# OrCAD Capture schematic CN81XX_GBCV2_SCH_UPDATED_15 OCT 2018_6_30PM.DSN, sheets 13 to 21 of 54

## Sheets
13 13.CN81XX CORE VDD: size B; title: CN81XX CORE VDD
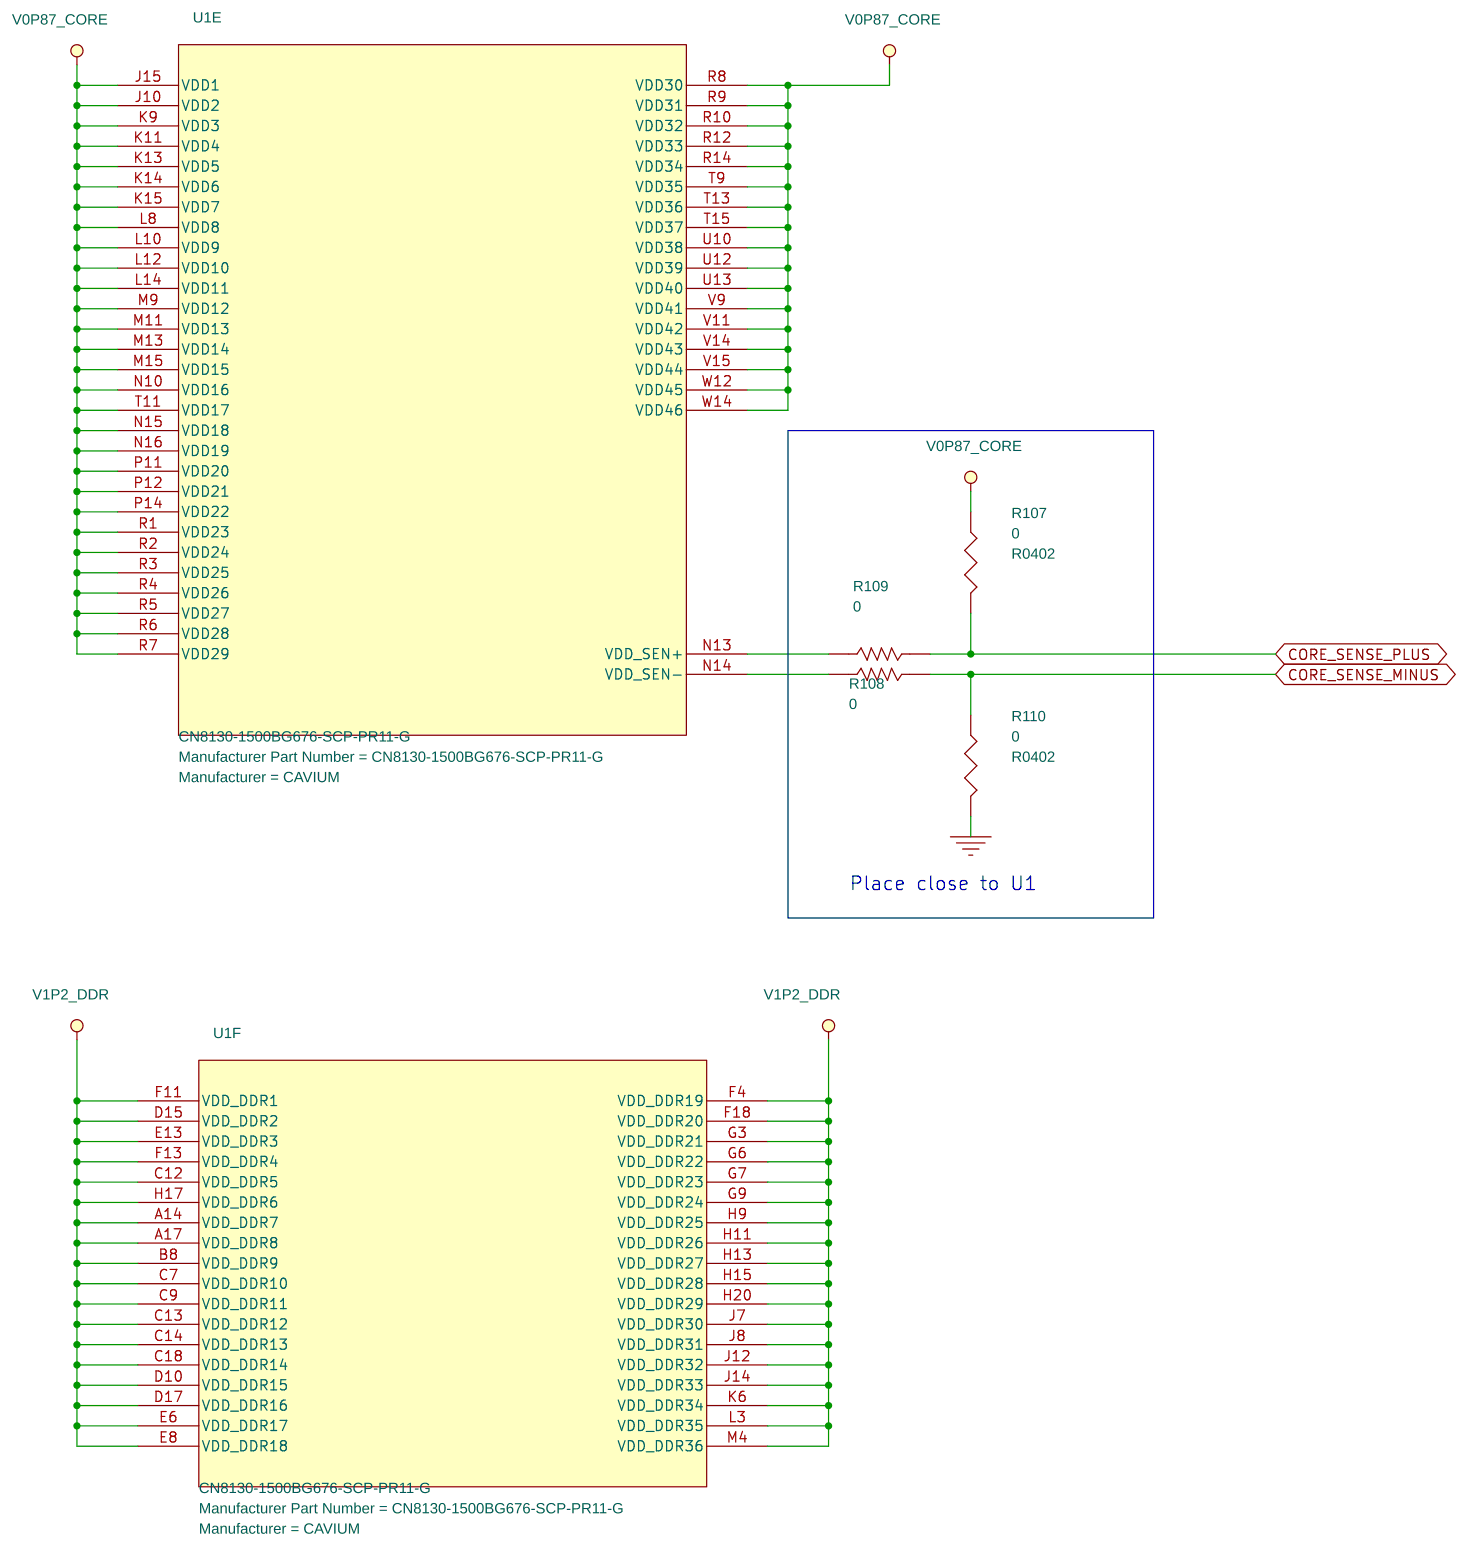
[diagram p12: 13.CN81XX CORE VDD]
14 15.CN81XX QLM & USB SUPPLY: size B; title: CN81XX QLM&USB SUPLY
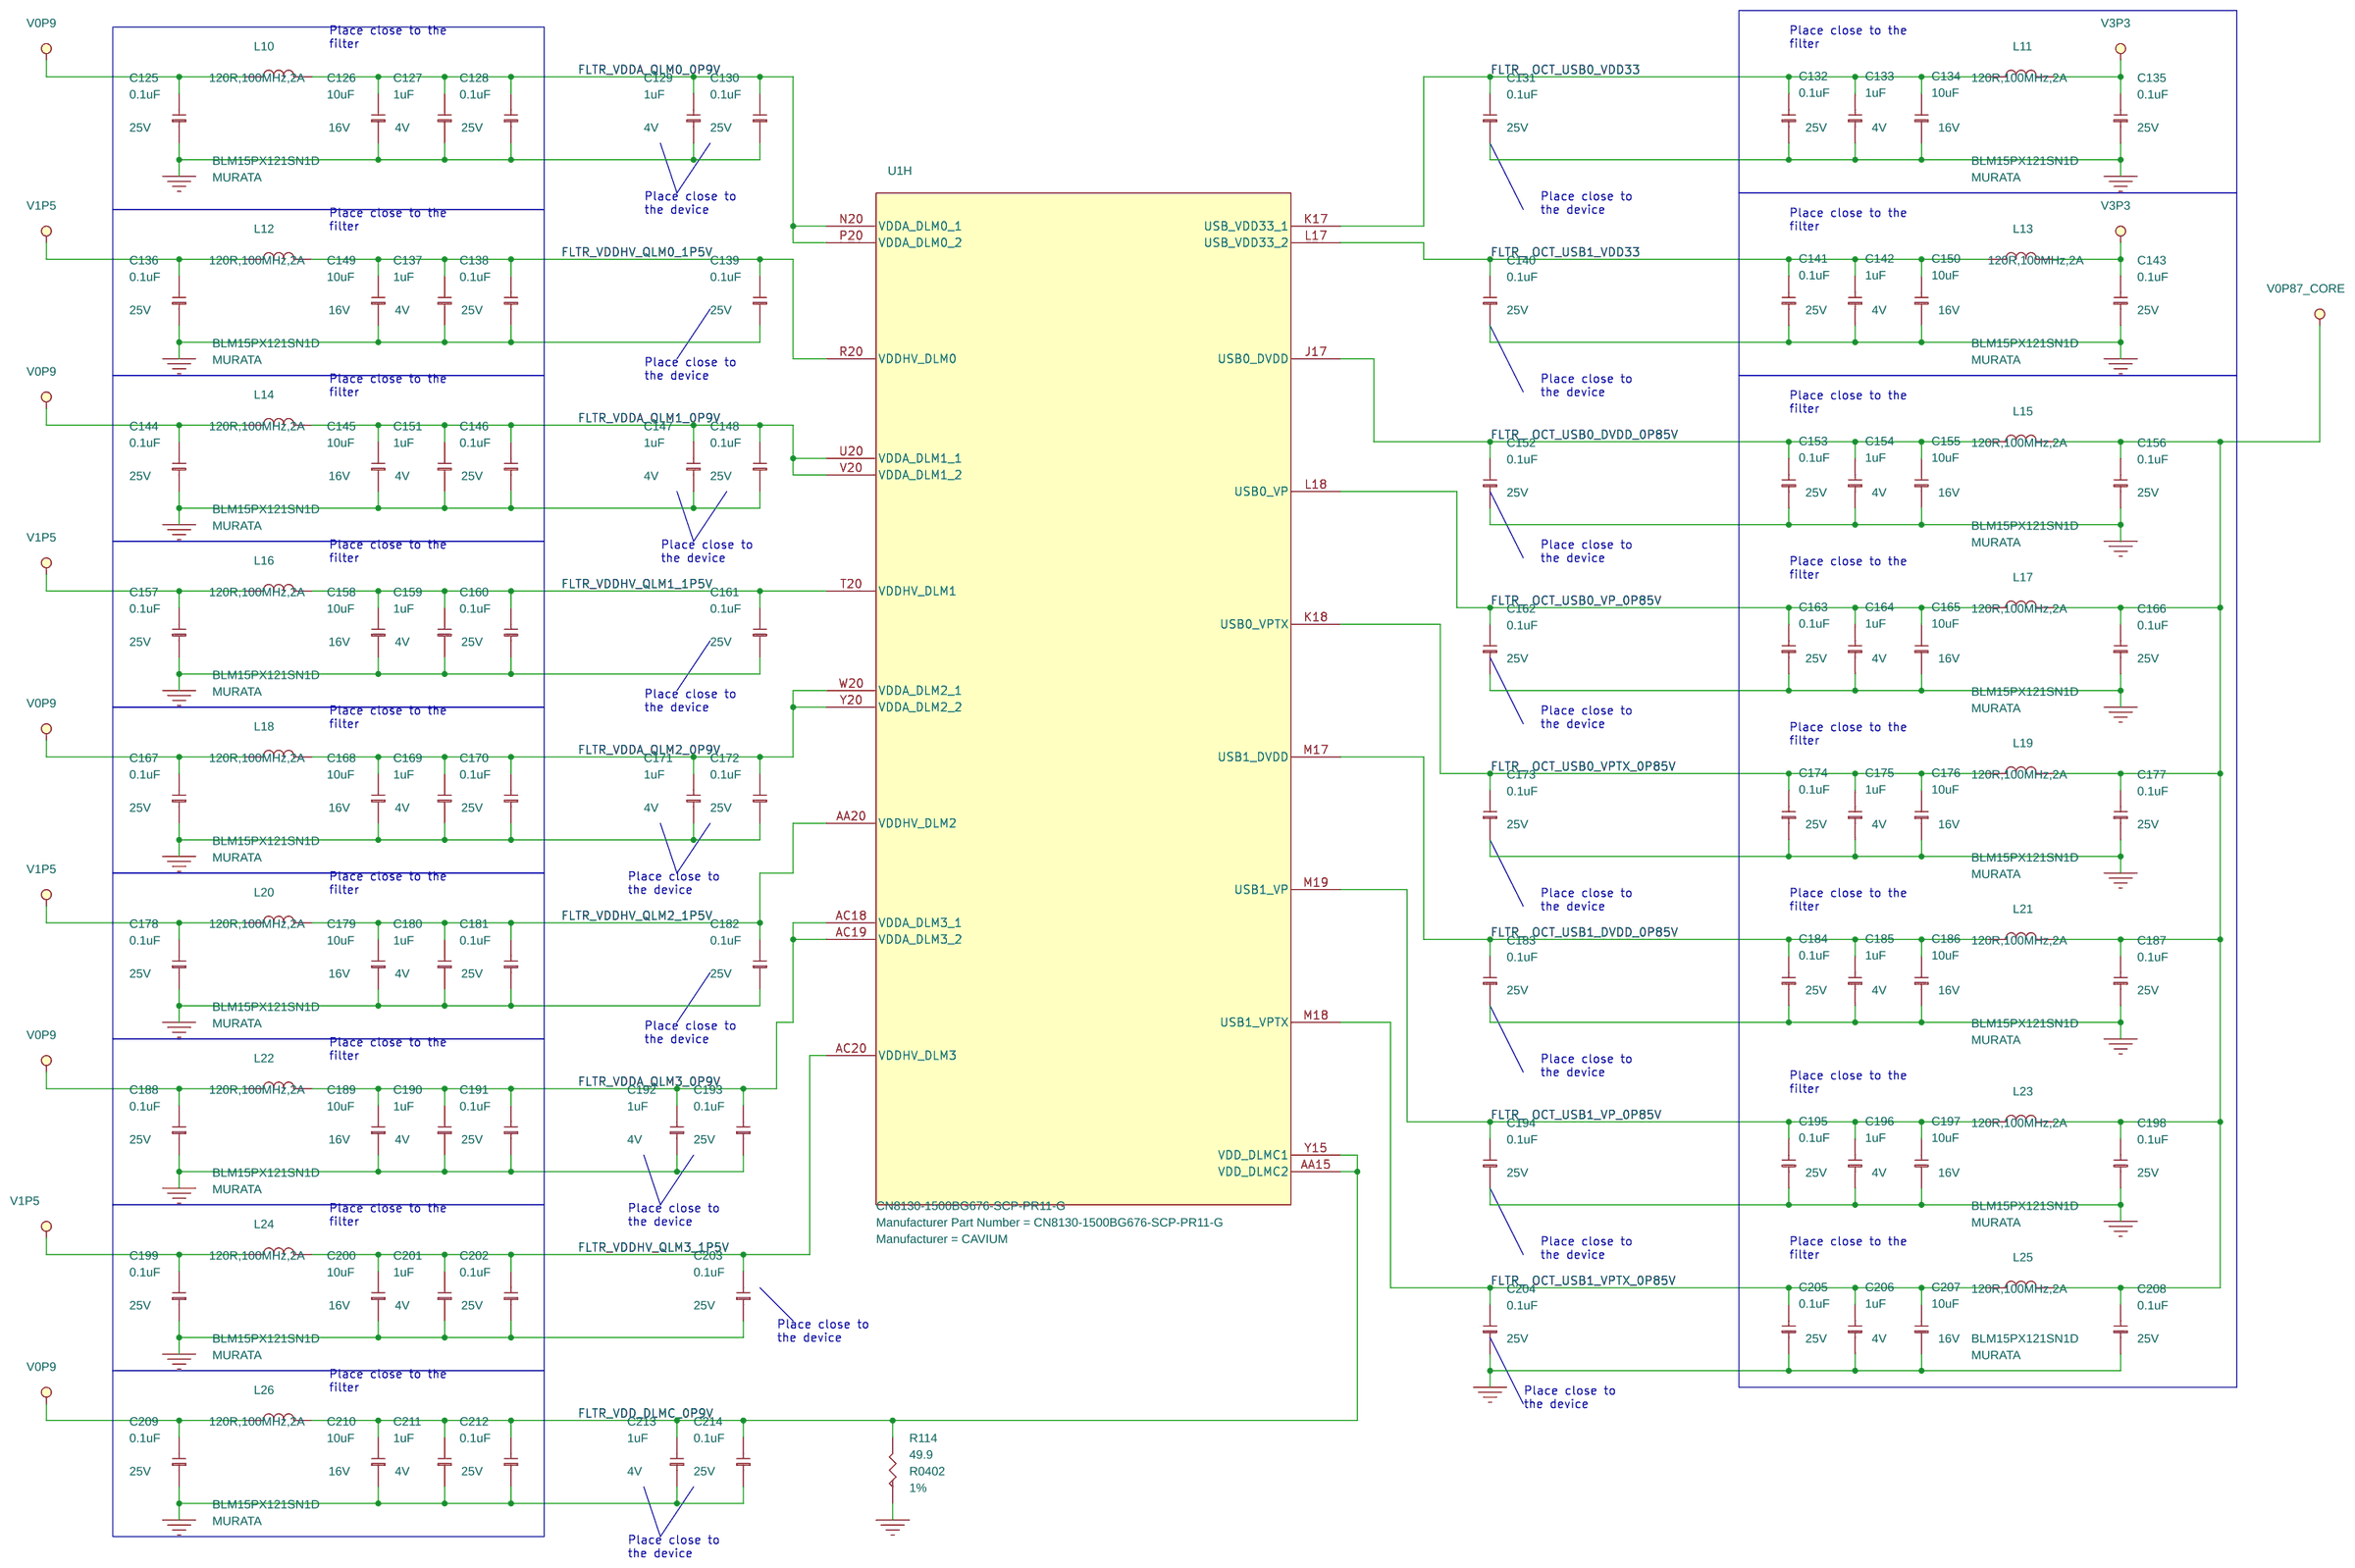
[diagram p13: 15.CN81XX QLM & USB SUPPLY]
15 16.CN81XX GND: size B; title: CN81XX GND
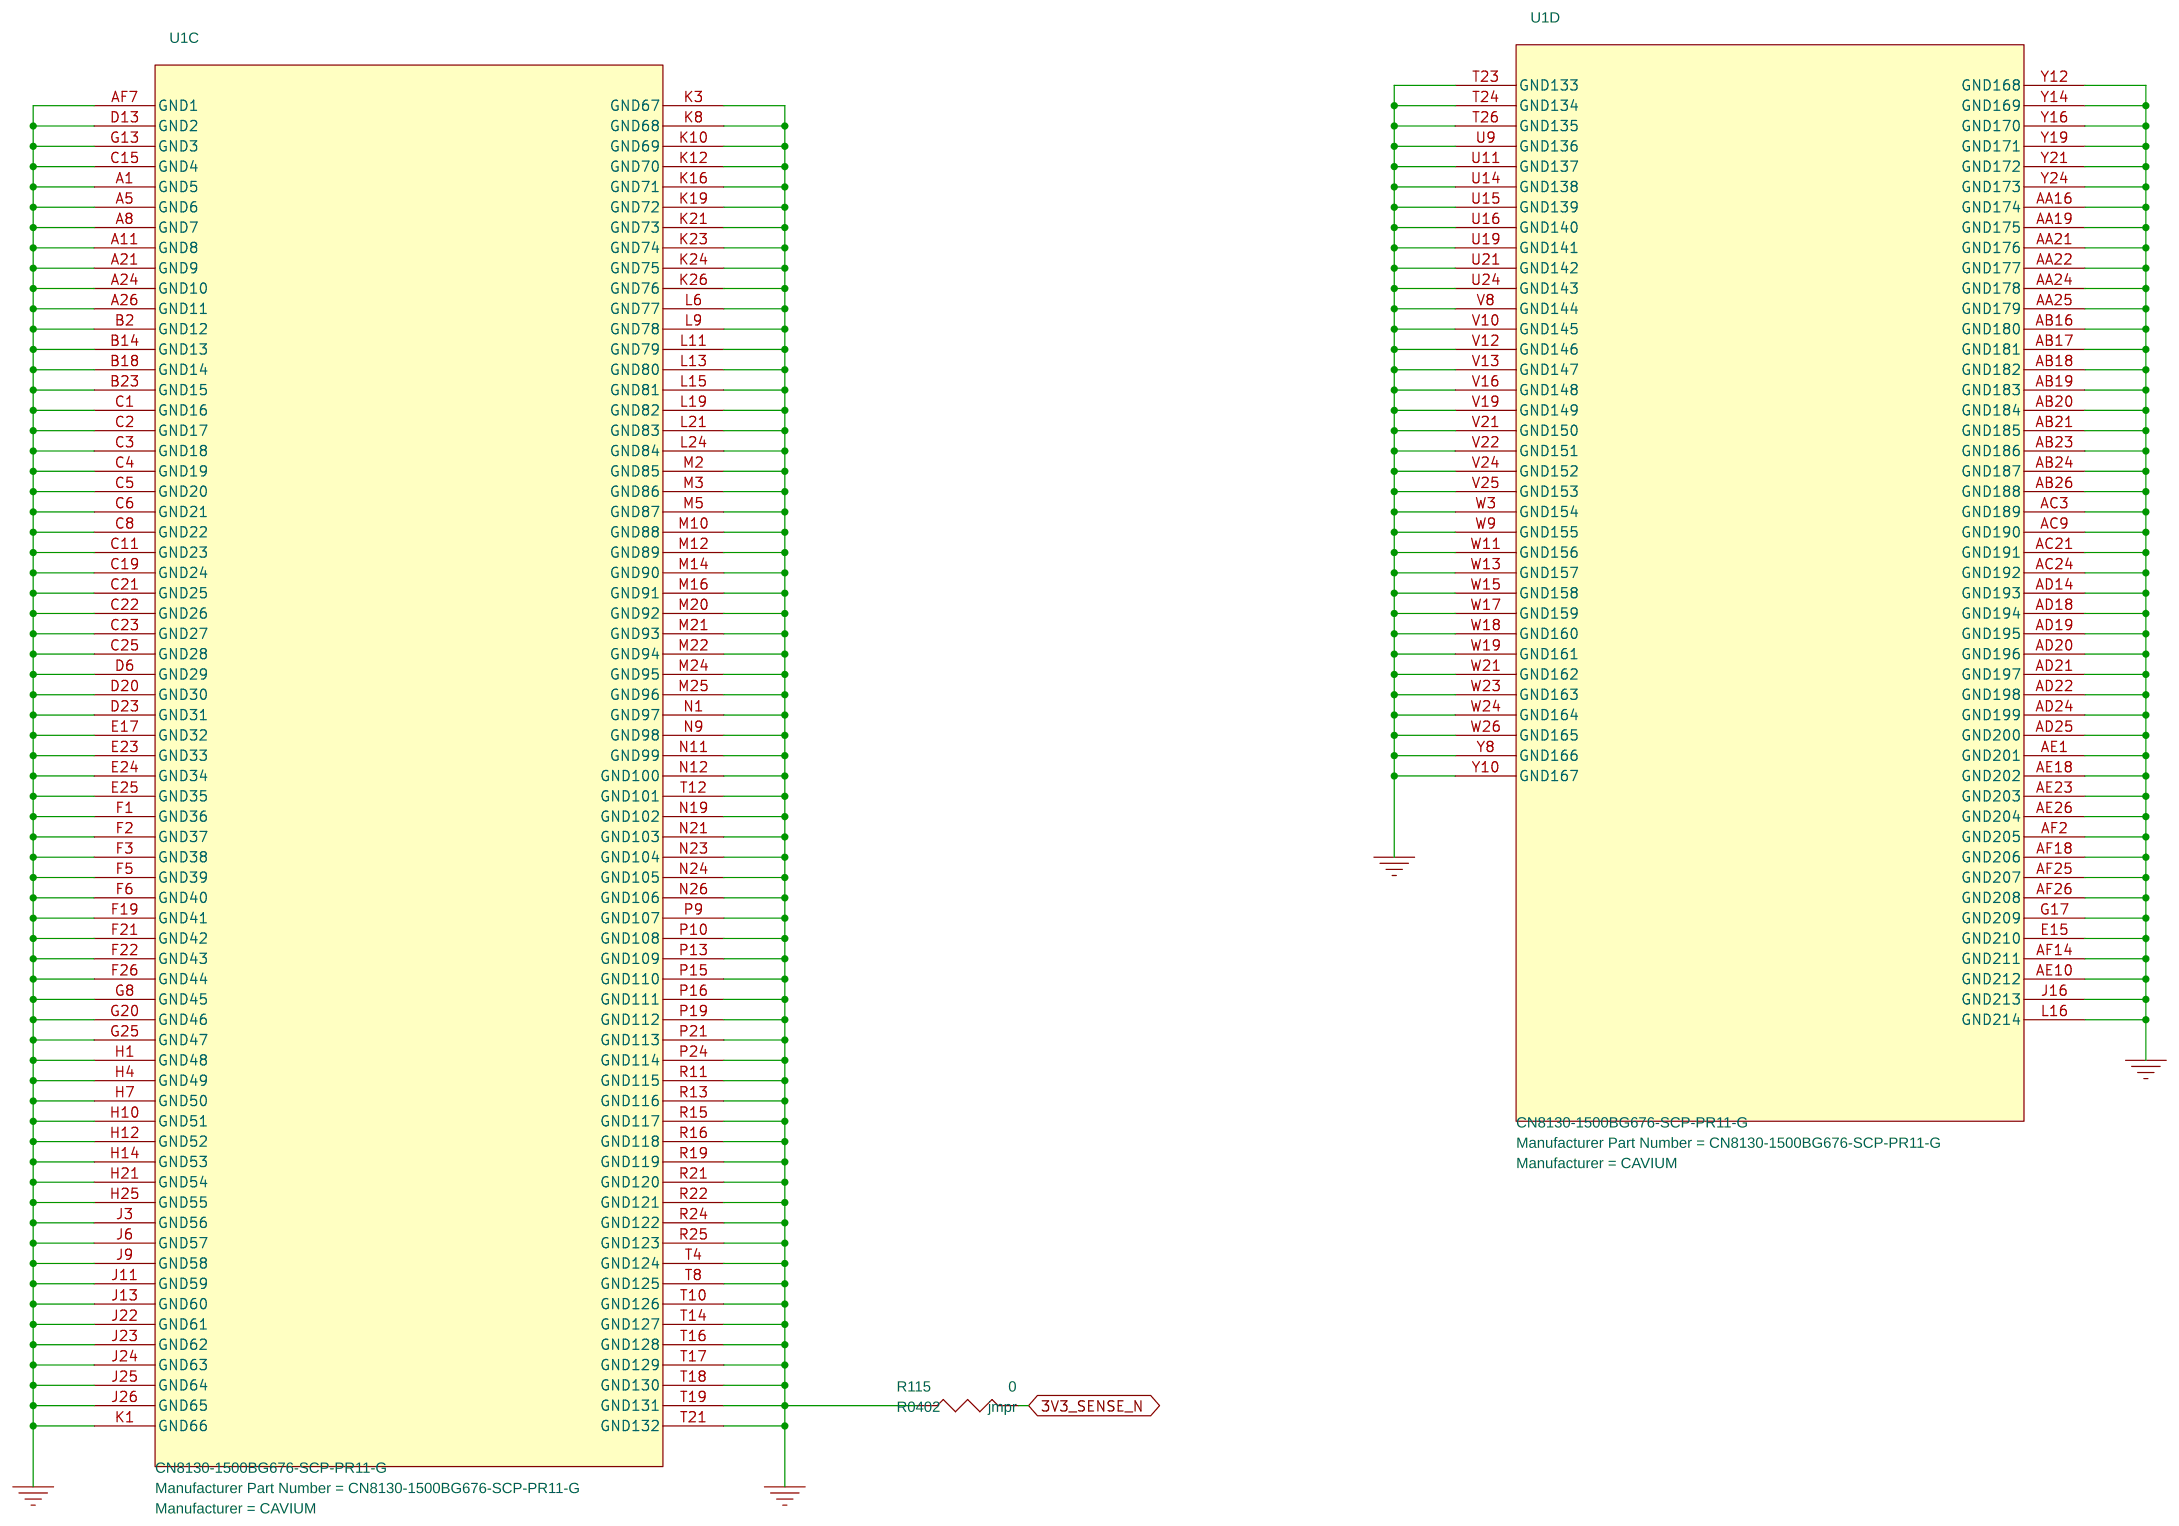
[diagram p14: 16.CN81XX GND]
16 17.CN81XX CORE & DDR DECOUPLING: size B; title: CN81XX CORE & DR DECOUPLING
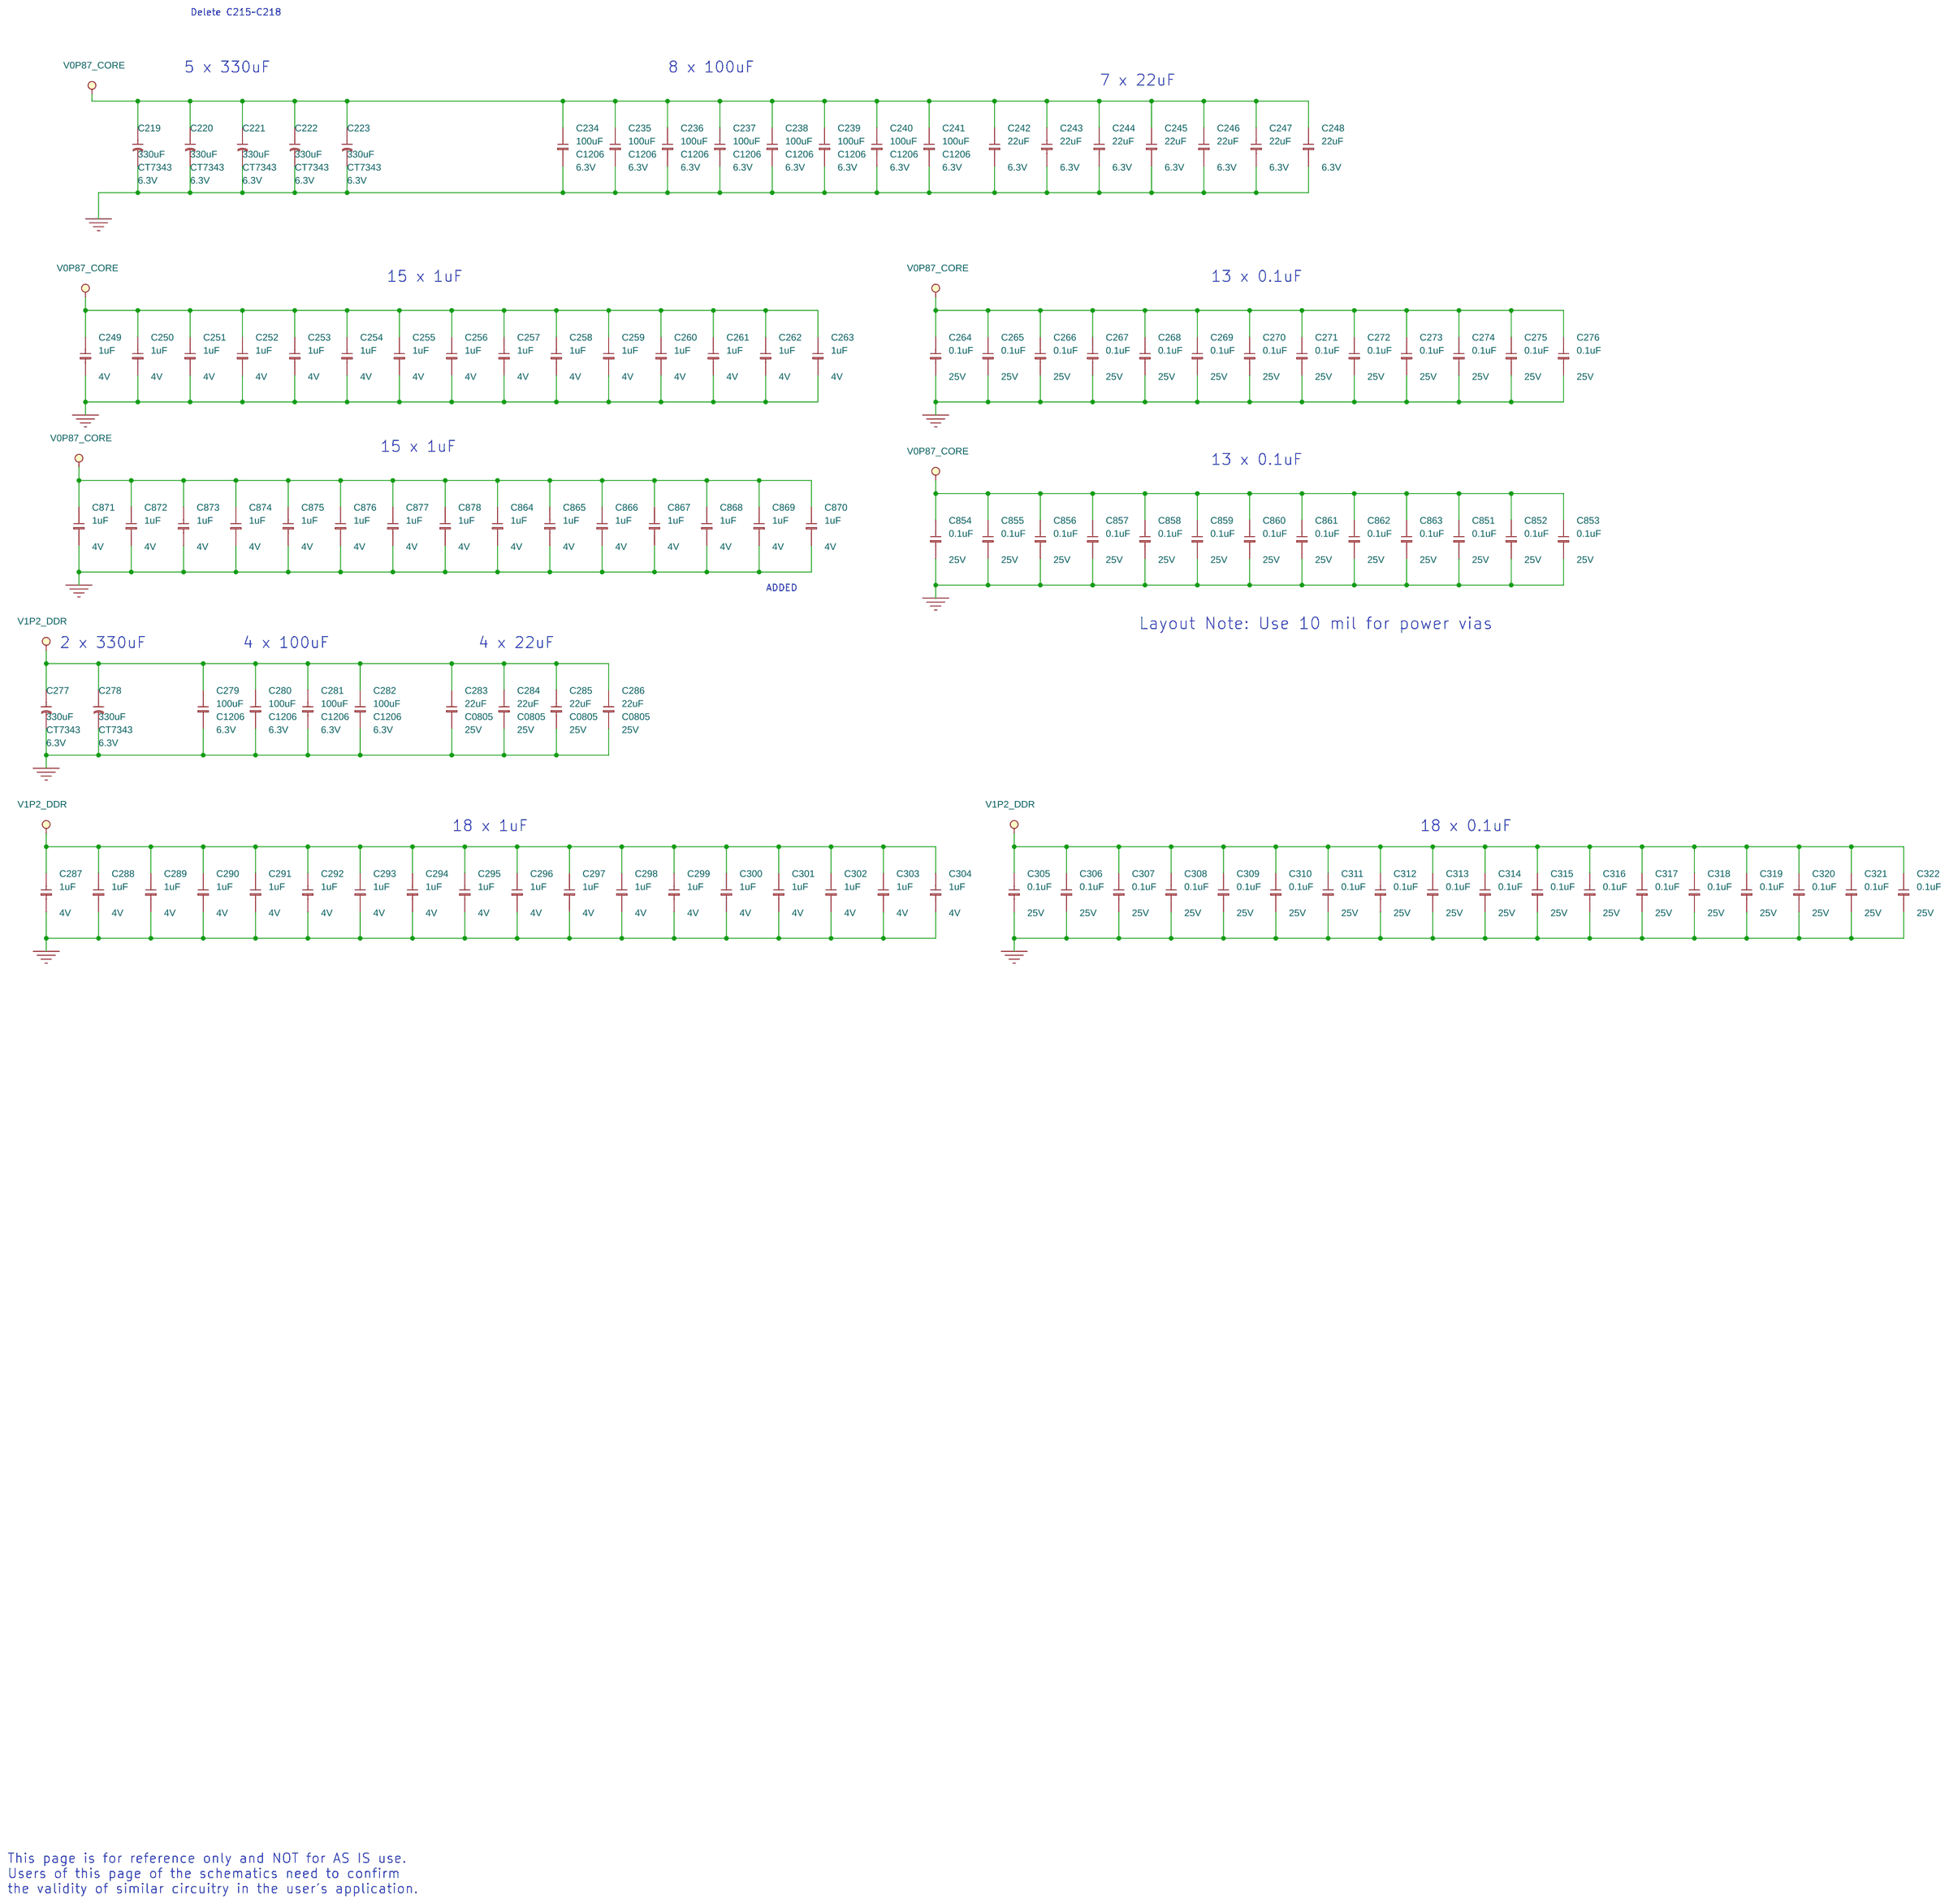
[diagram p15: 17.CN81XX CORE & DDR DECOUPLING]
17 18.CN81XX STRAPPING: size B; title: CN81XX STRAPPING
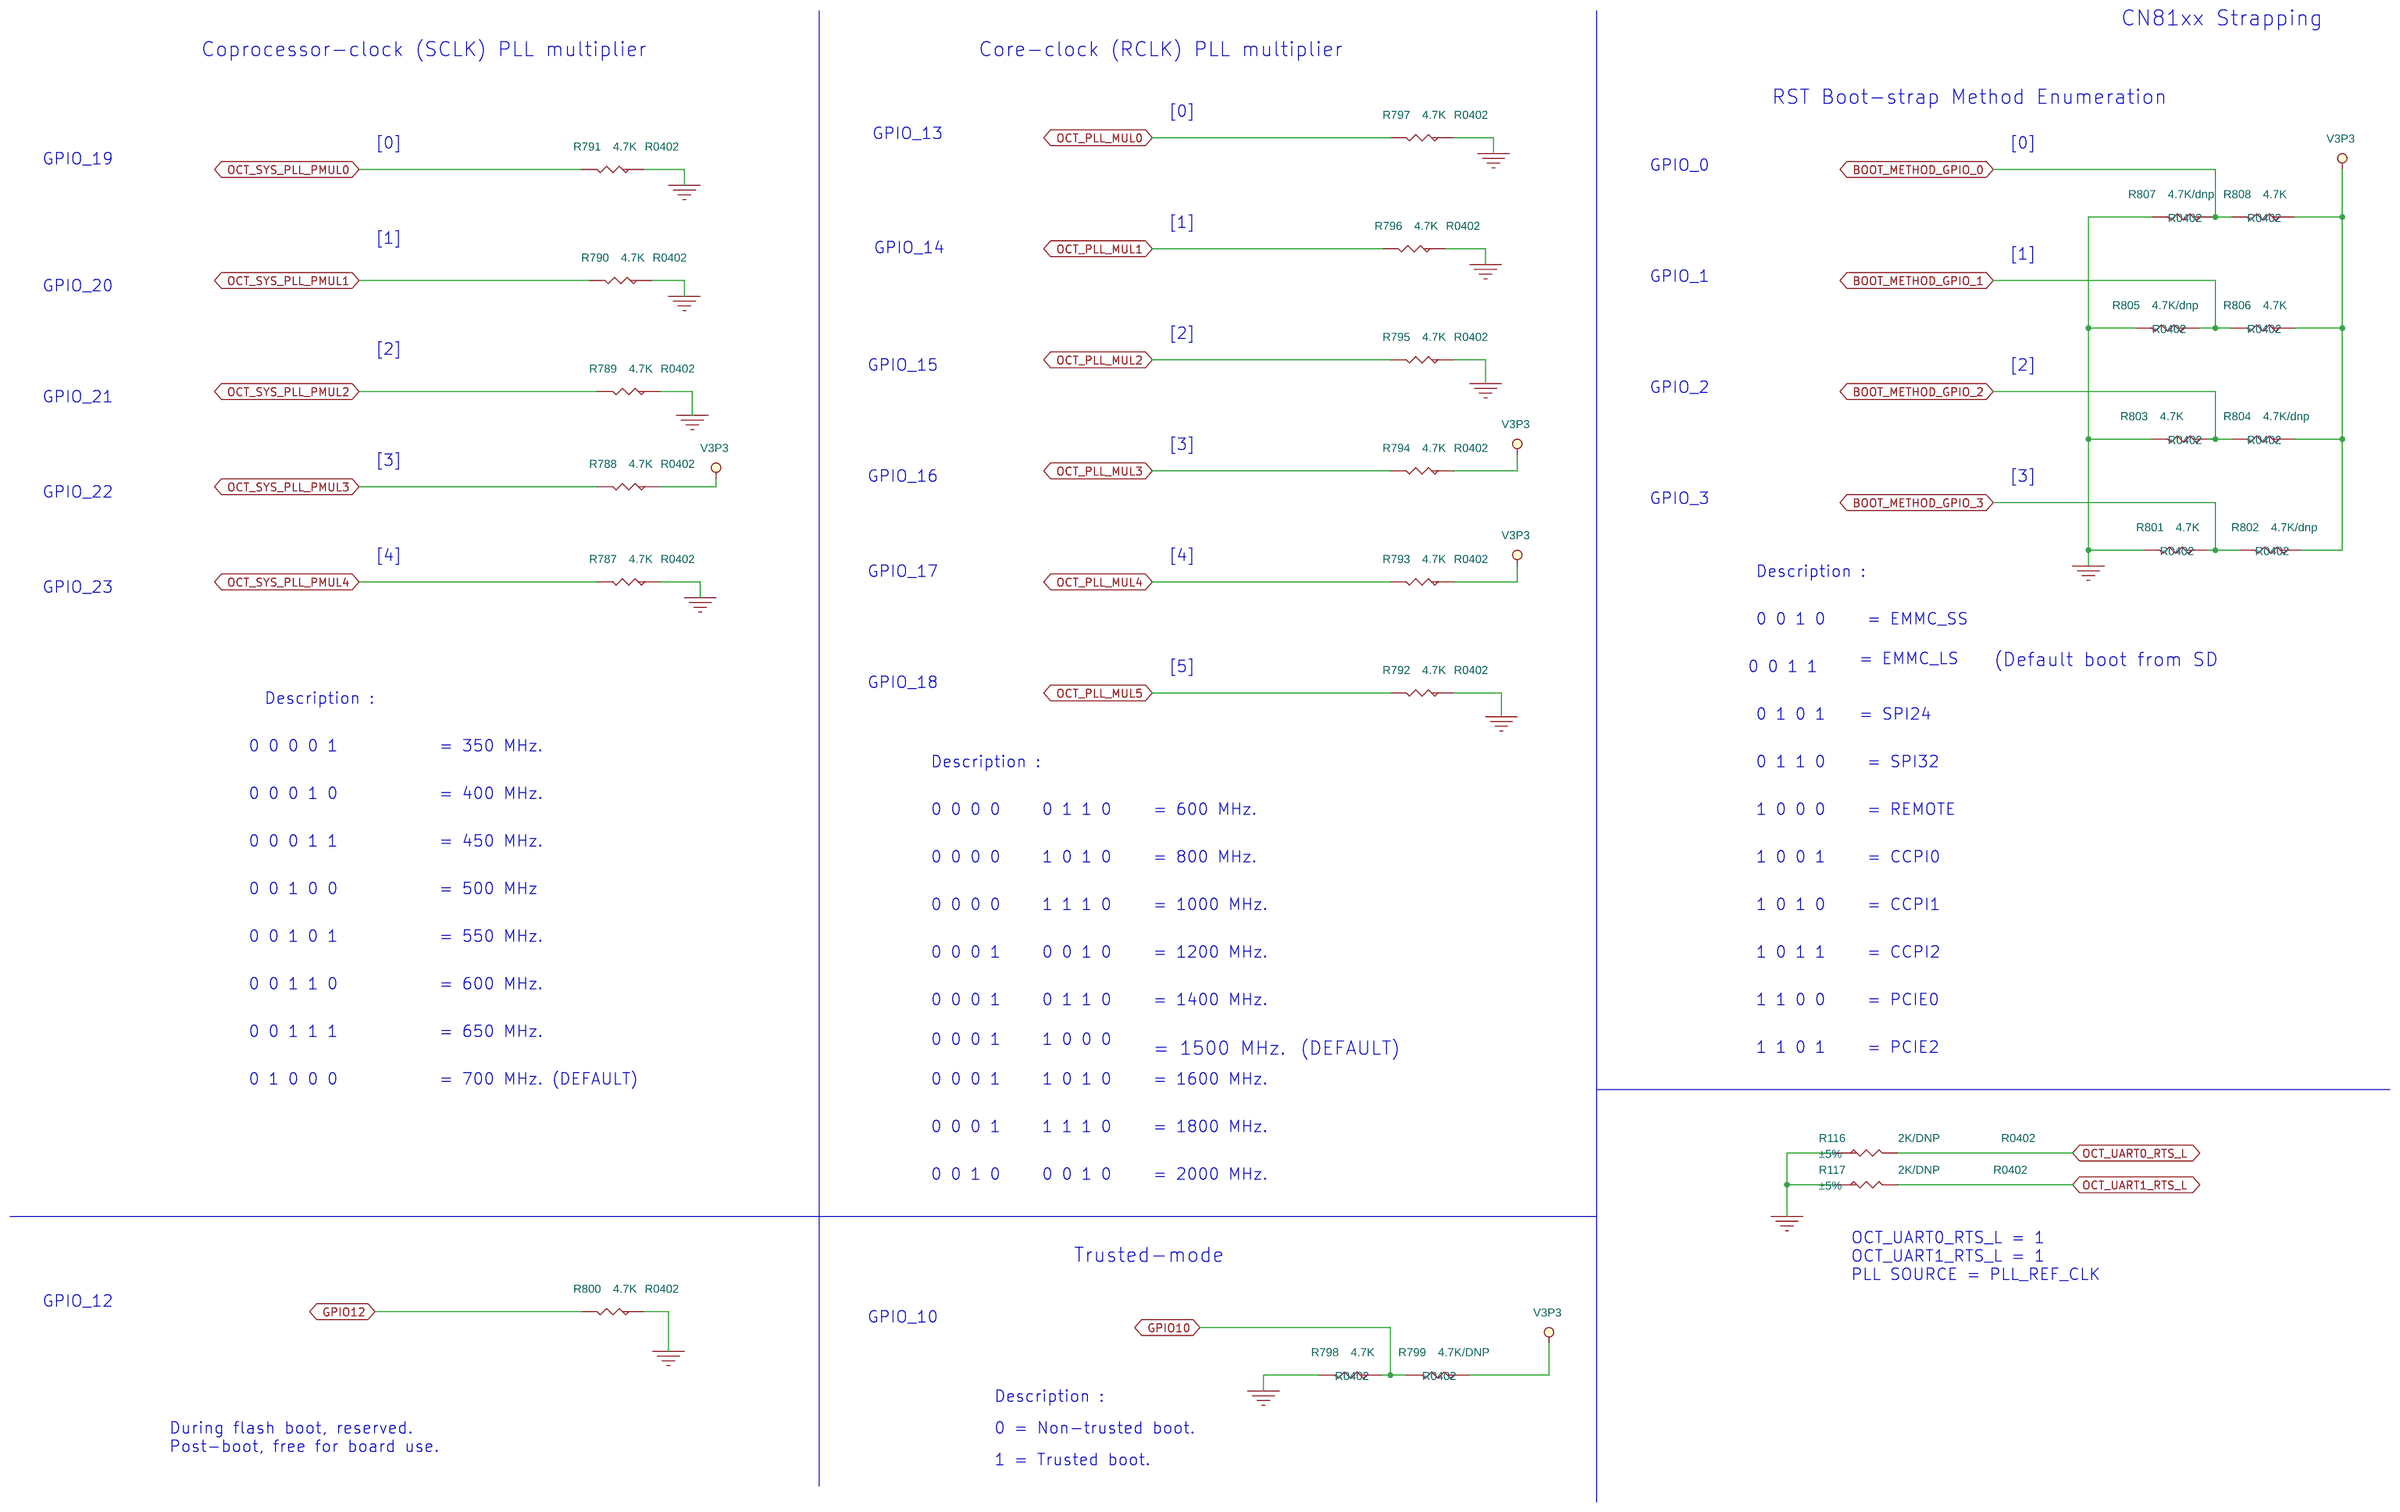
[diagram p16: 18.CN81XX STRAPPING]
18 19.RTC & THERMAL SENSORS: size B; title: RTC & THERMAL SENSORS
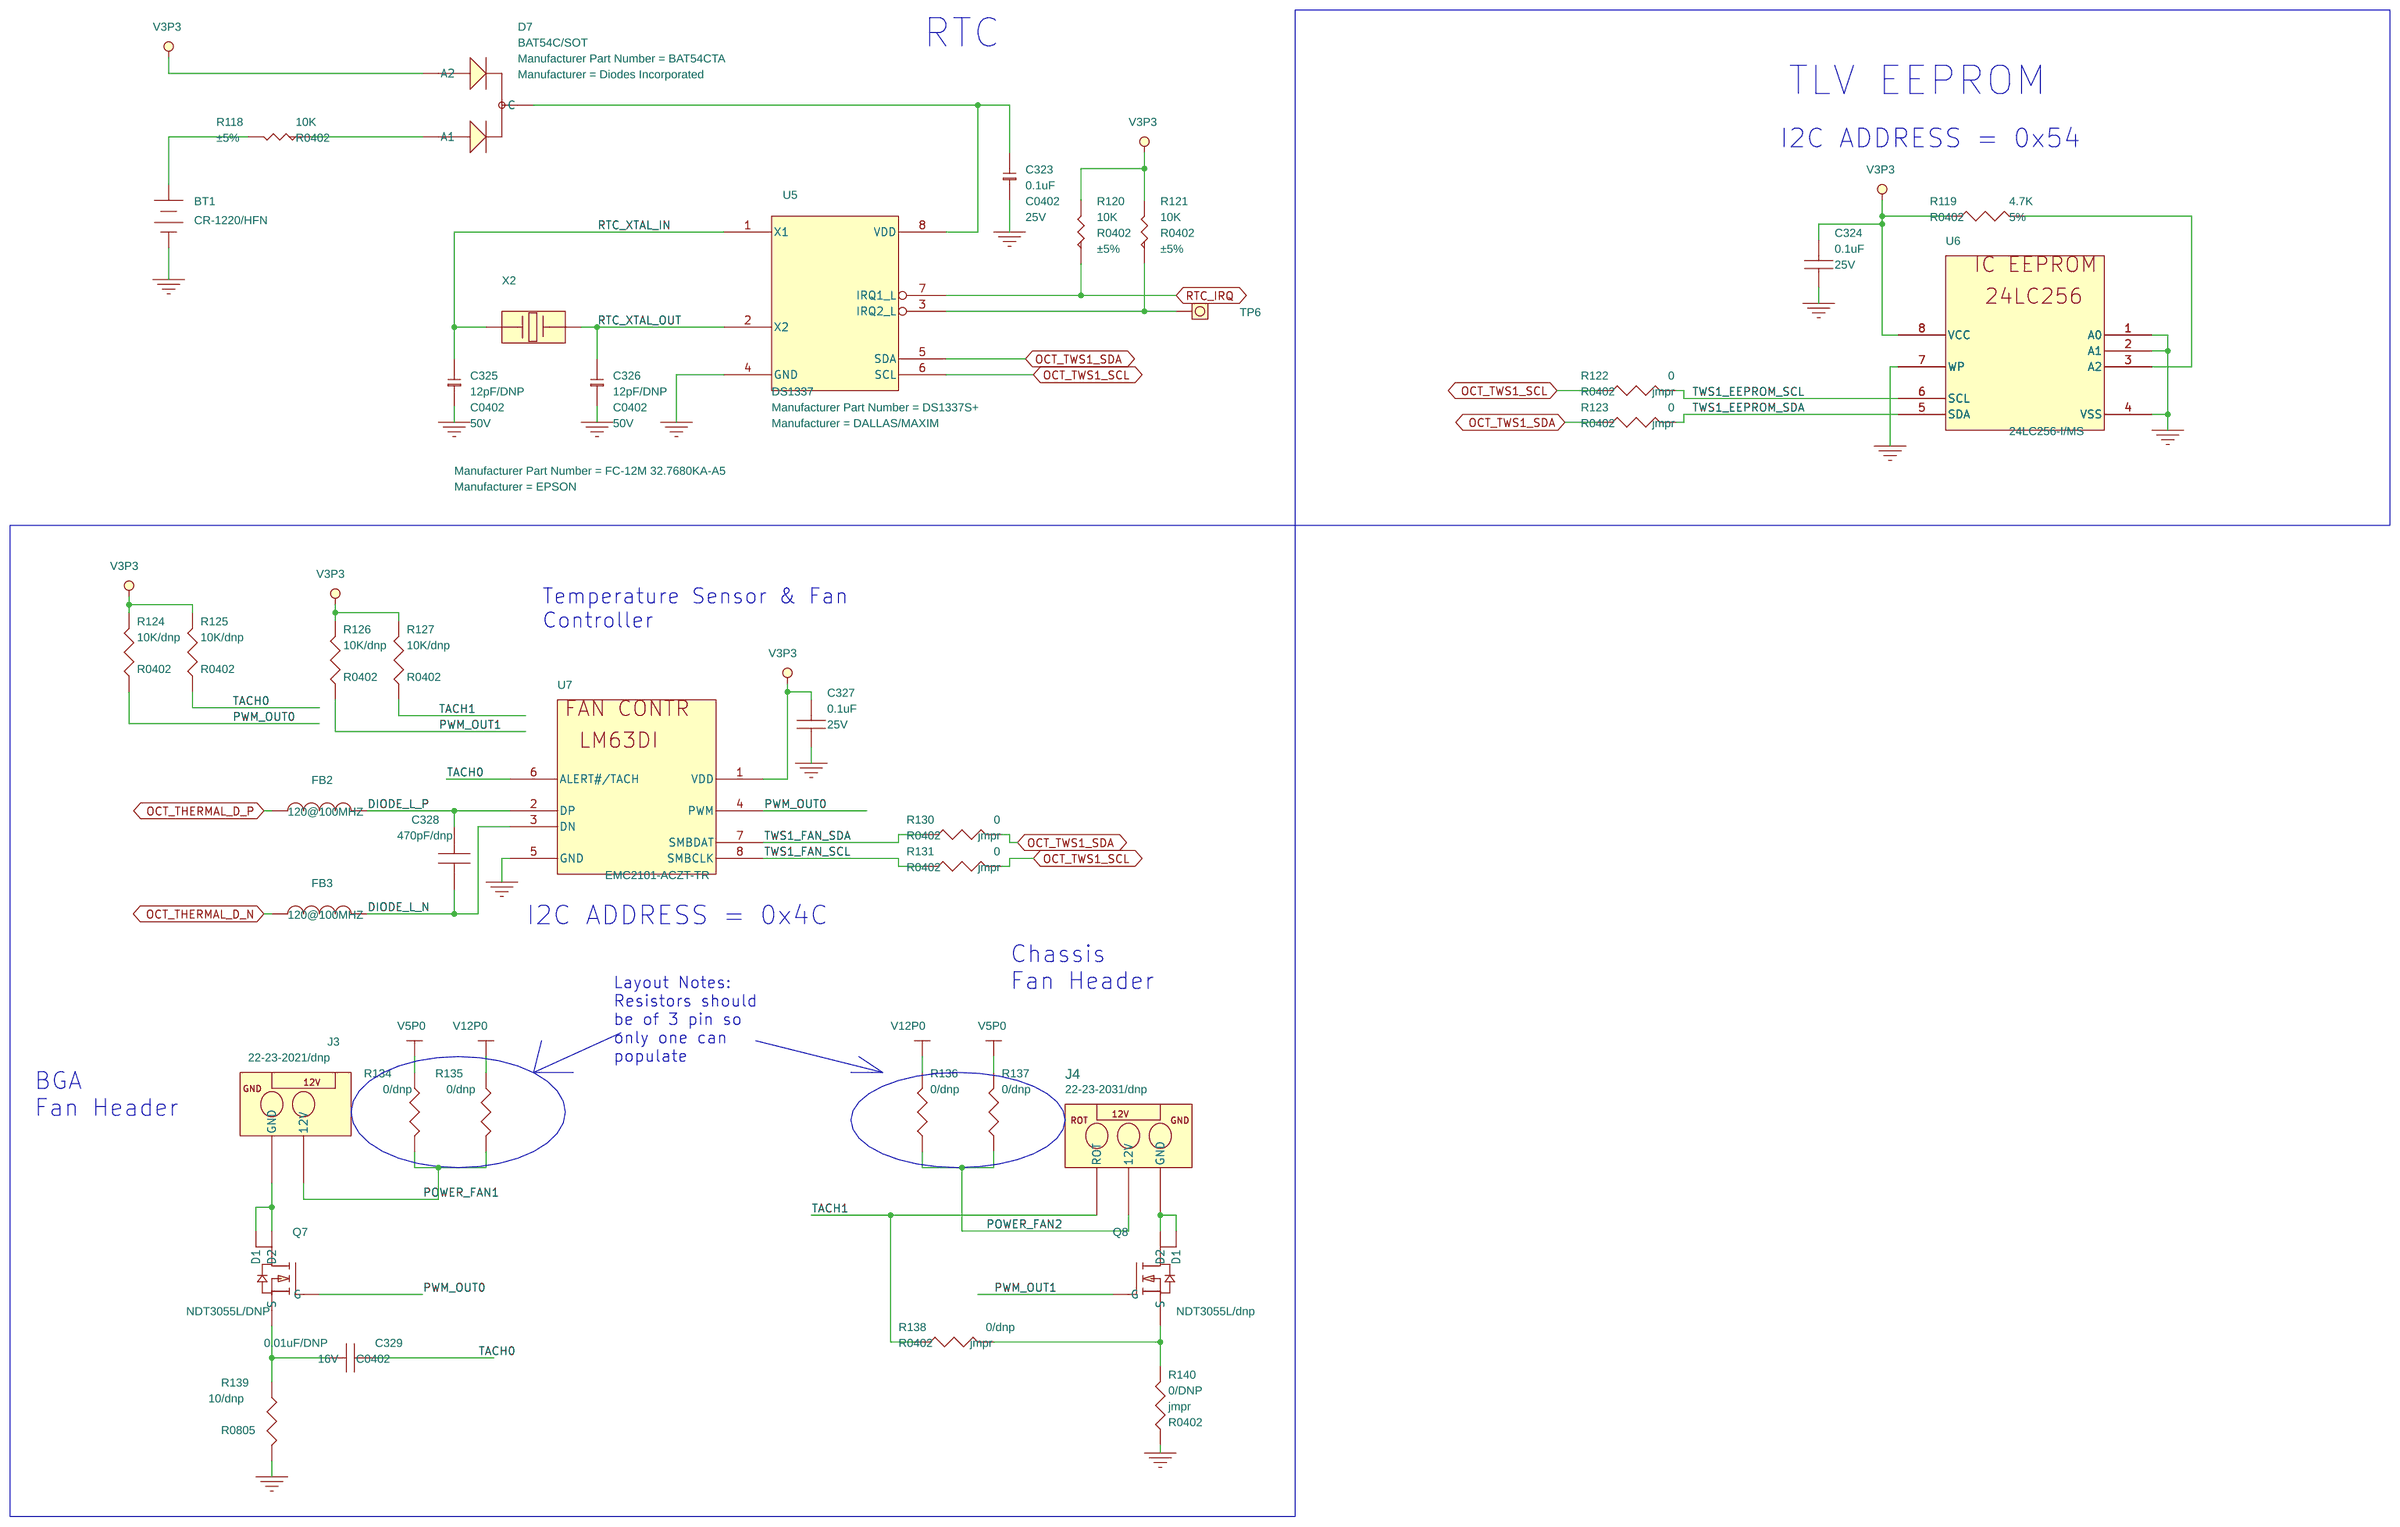
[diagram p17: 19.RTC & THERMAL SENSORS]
19 20.ETHERNET SWITCH: size Custom; title: ETHERNET SWITCH
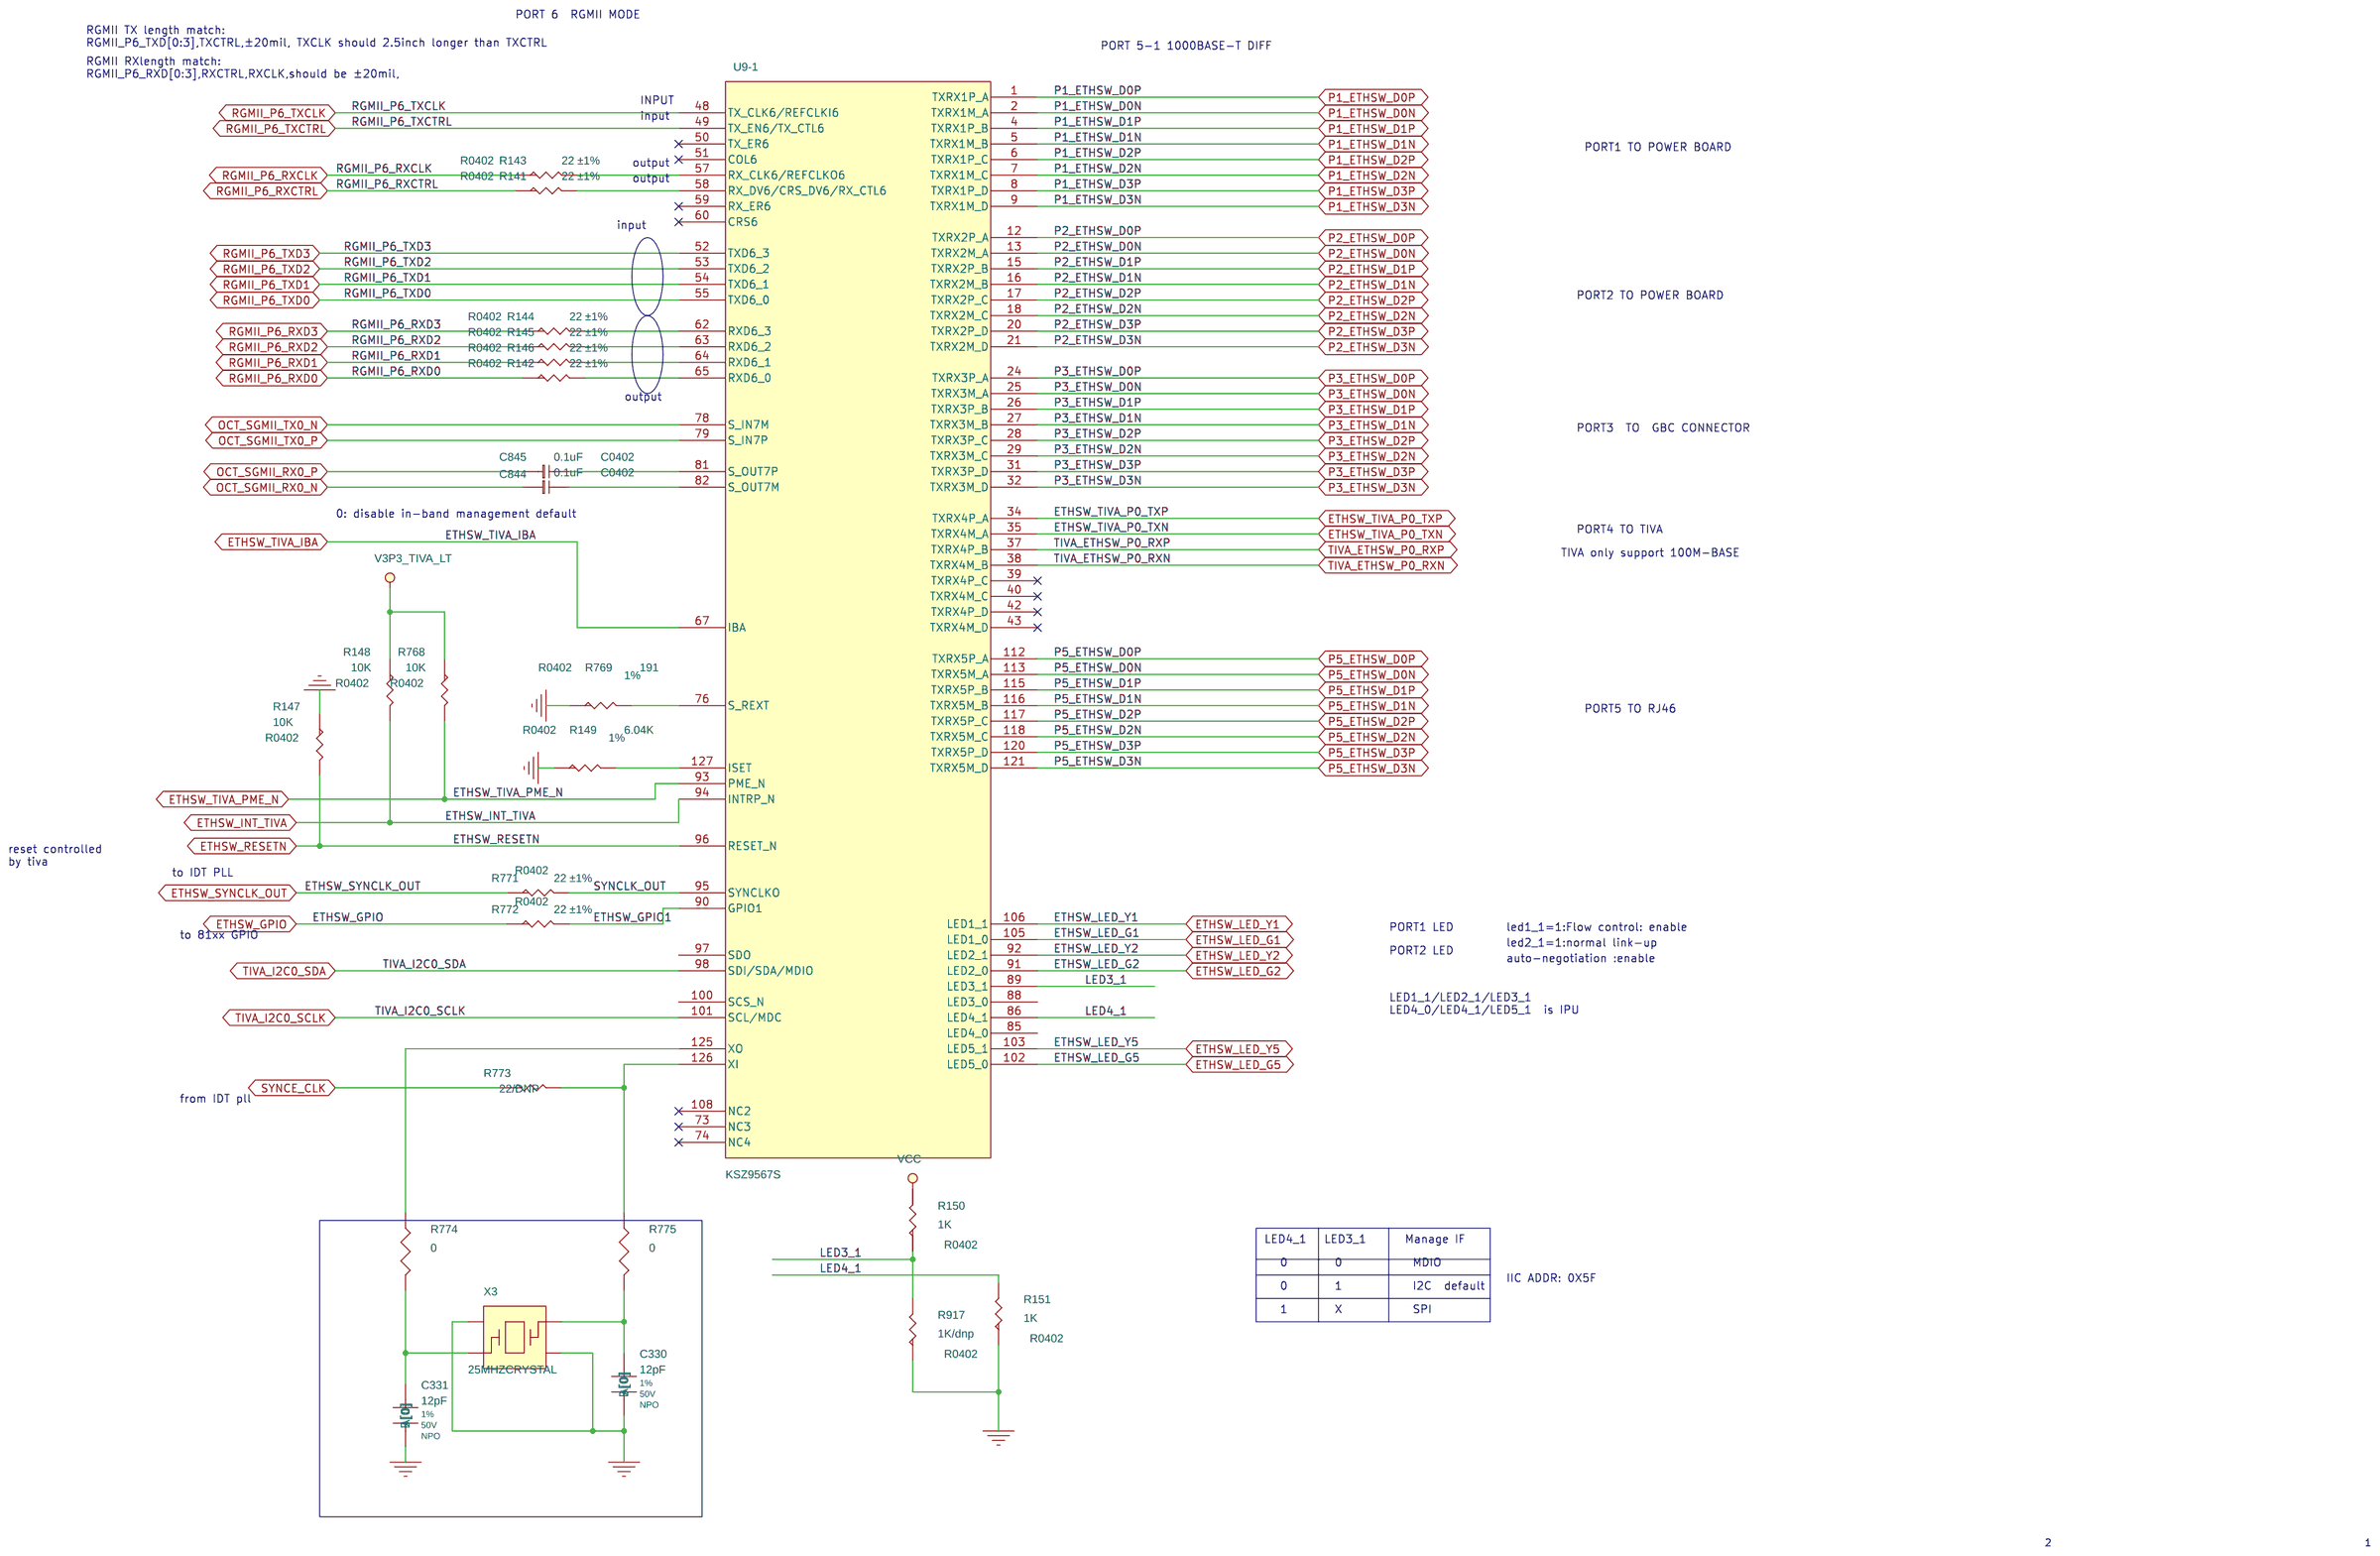
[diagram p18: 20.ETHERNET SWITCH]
20 21.ETHERNET SWITCH POWER: size A4; title: ETH PORT3
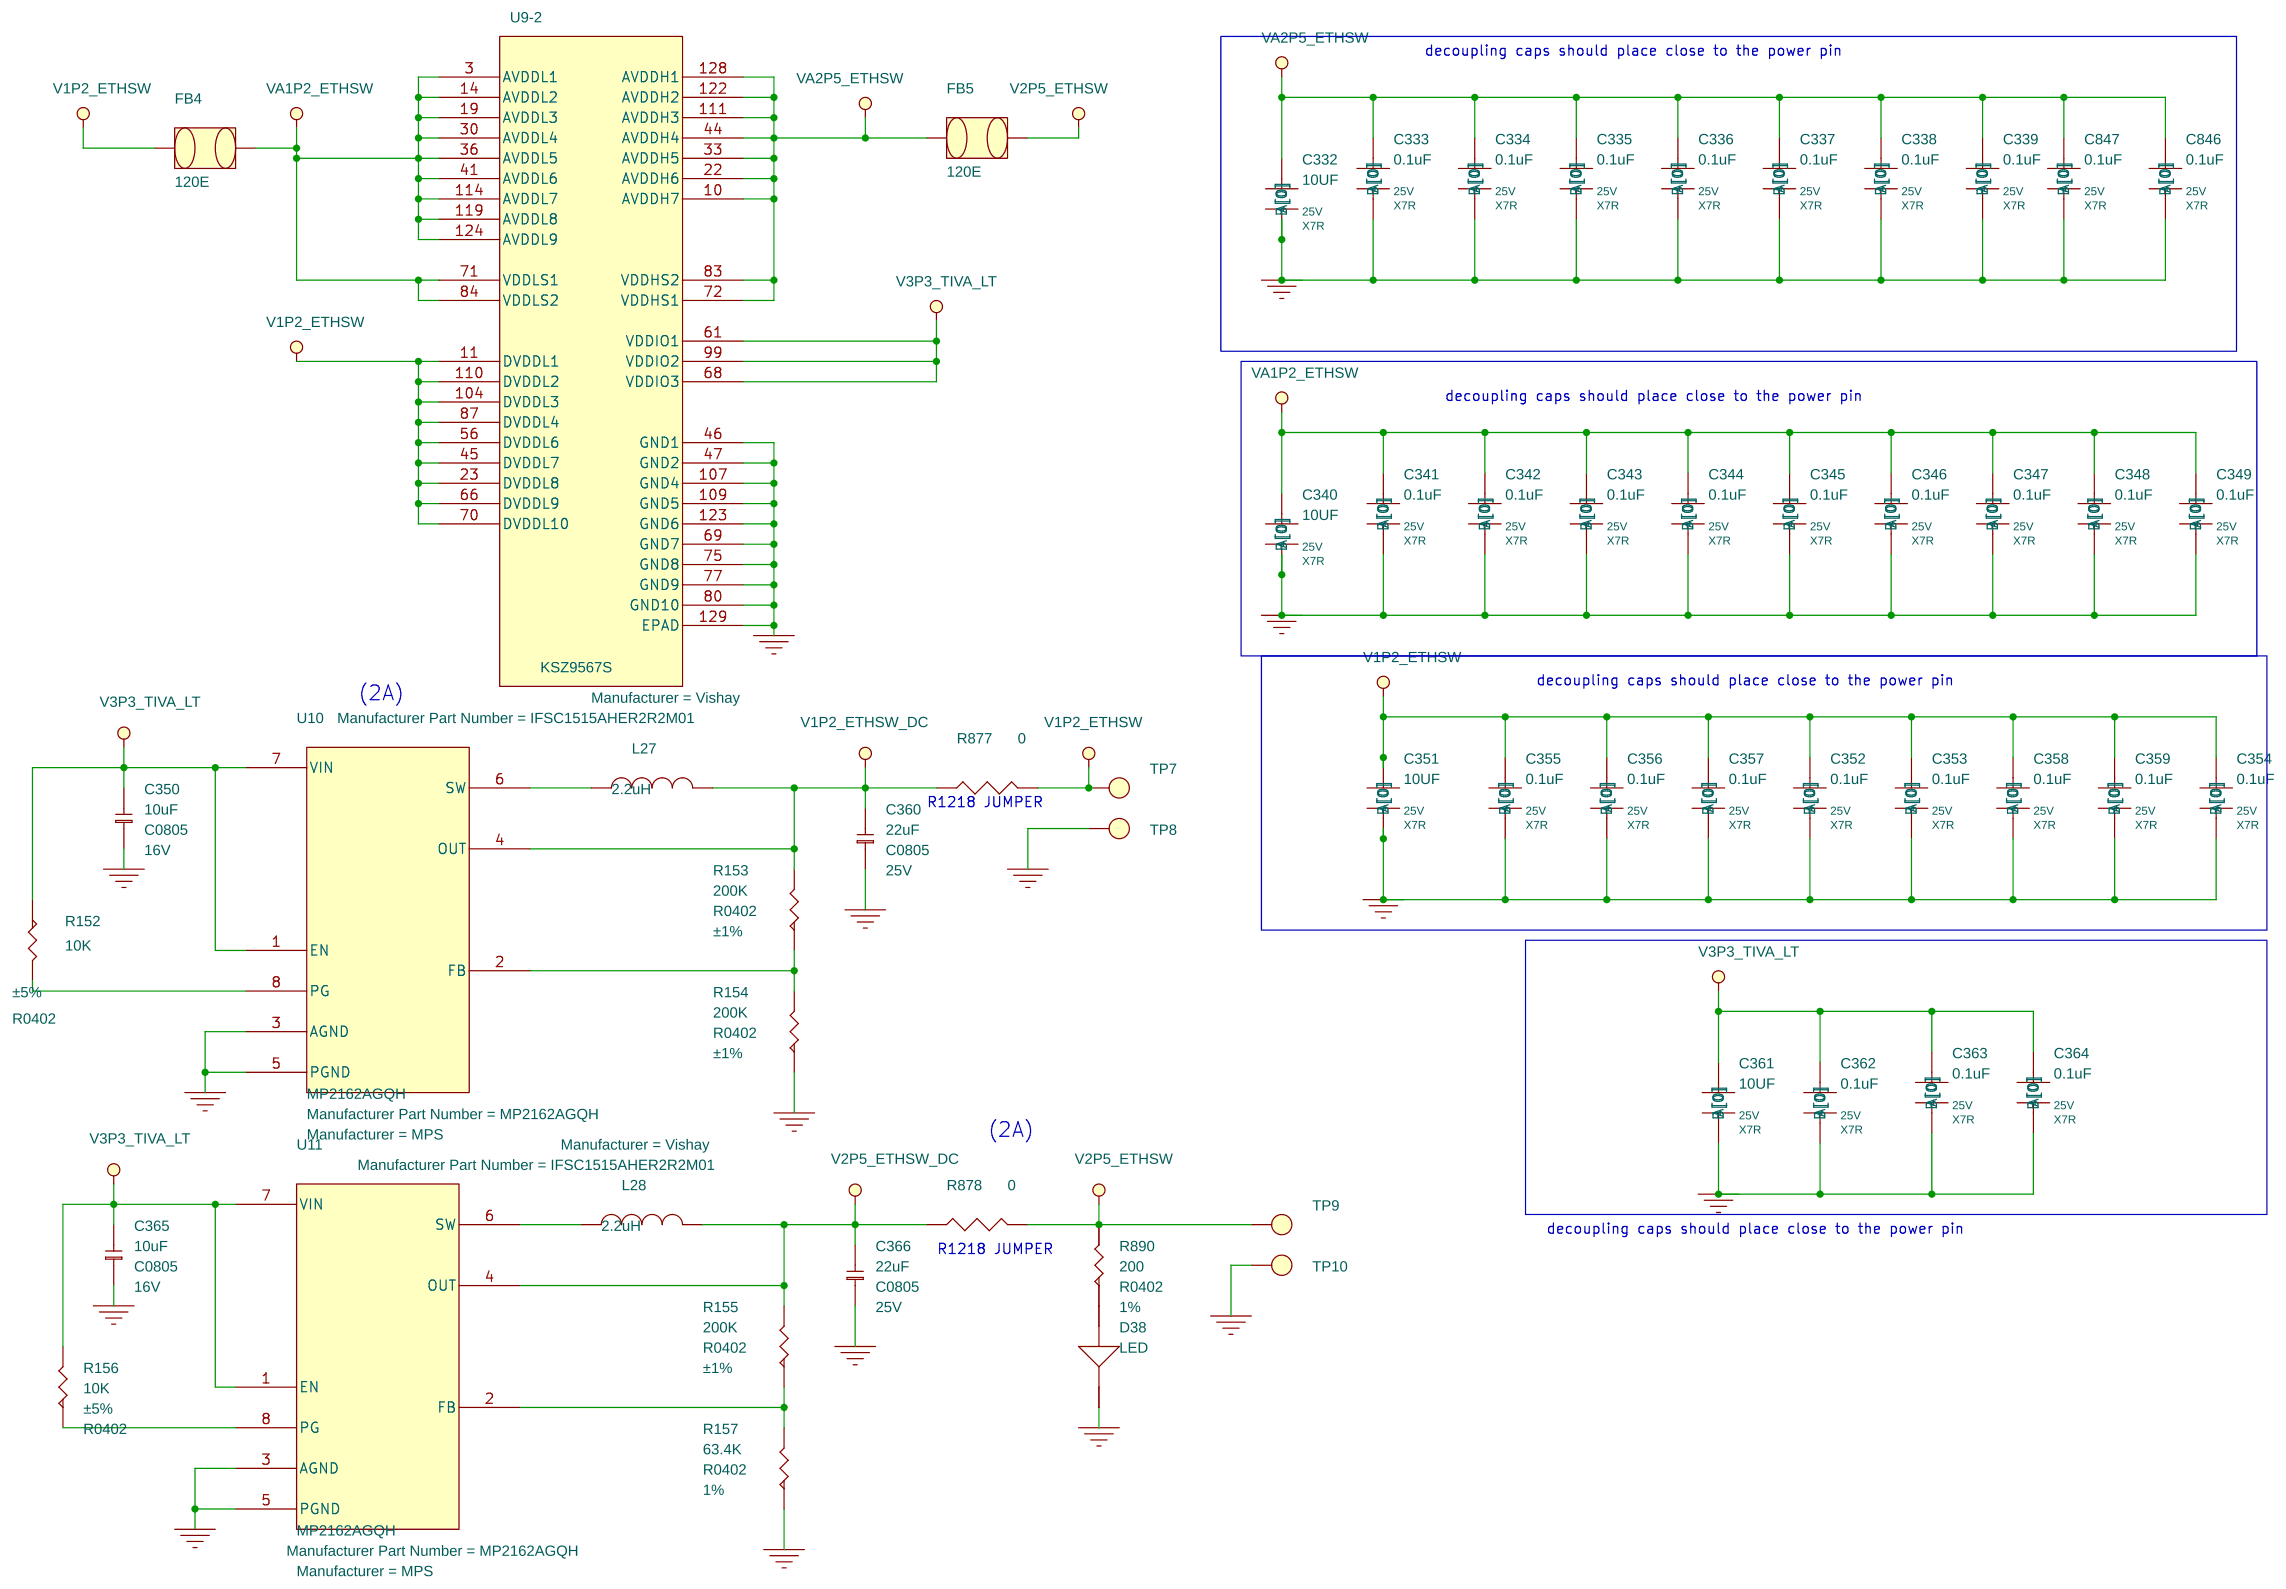
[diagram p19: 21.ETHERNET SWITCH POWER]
21 22.RJ45  PORT 0-1-5: size Custom; title: RJ45 PORT0
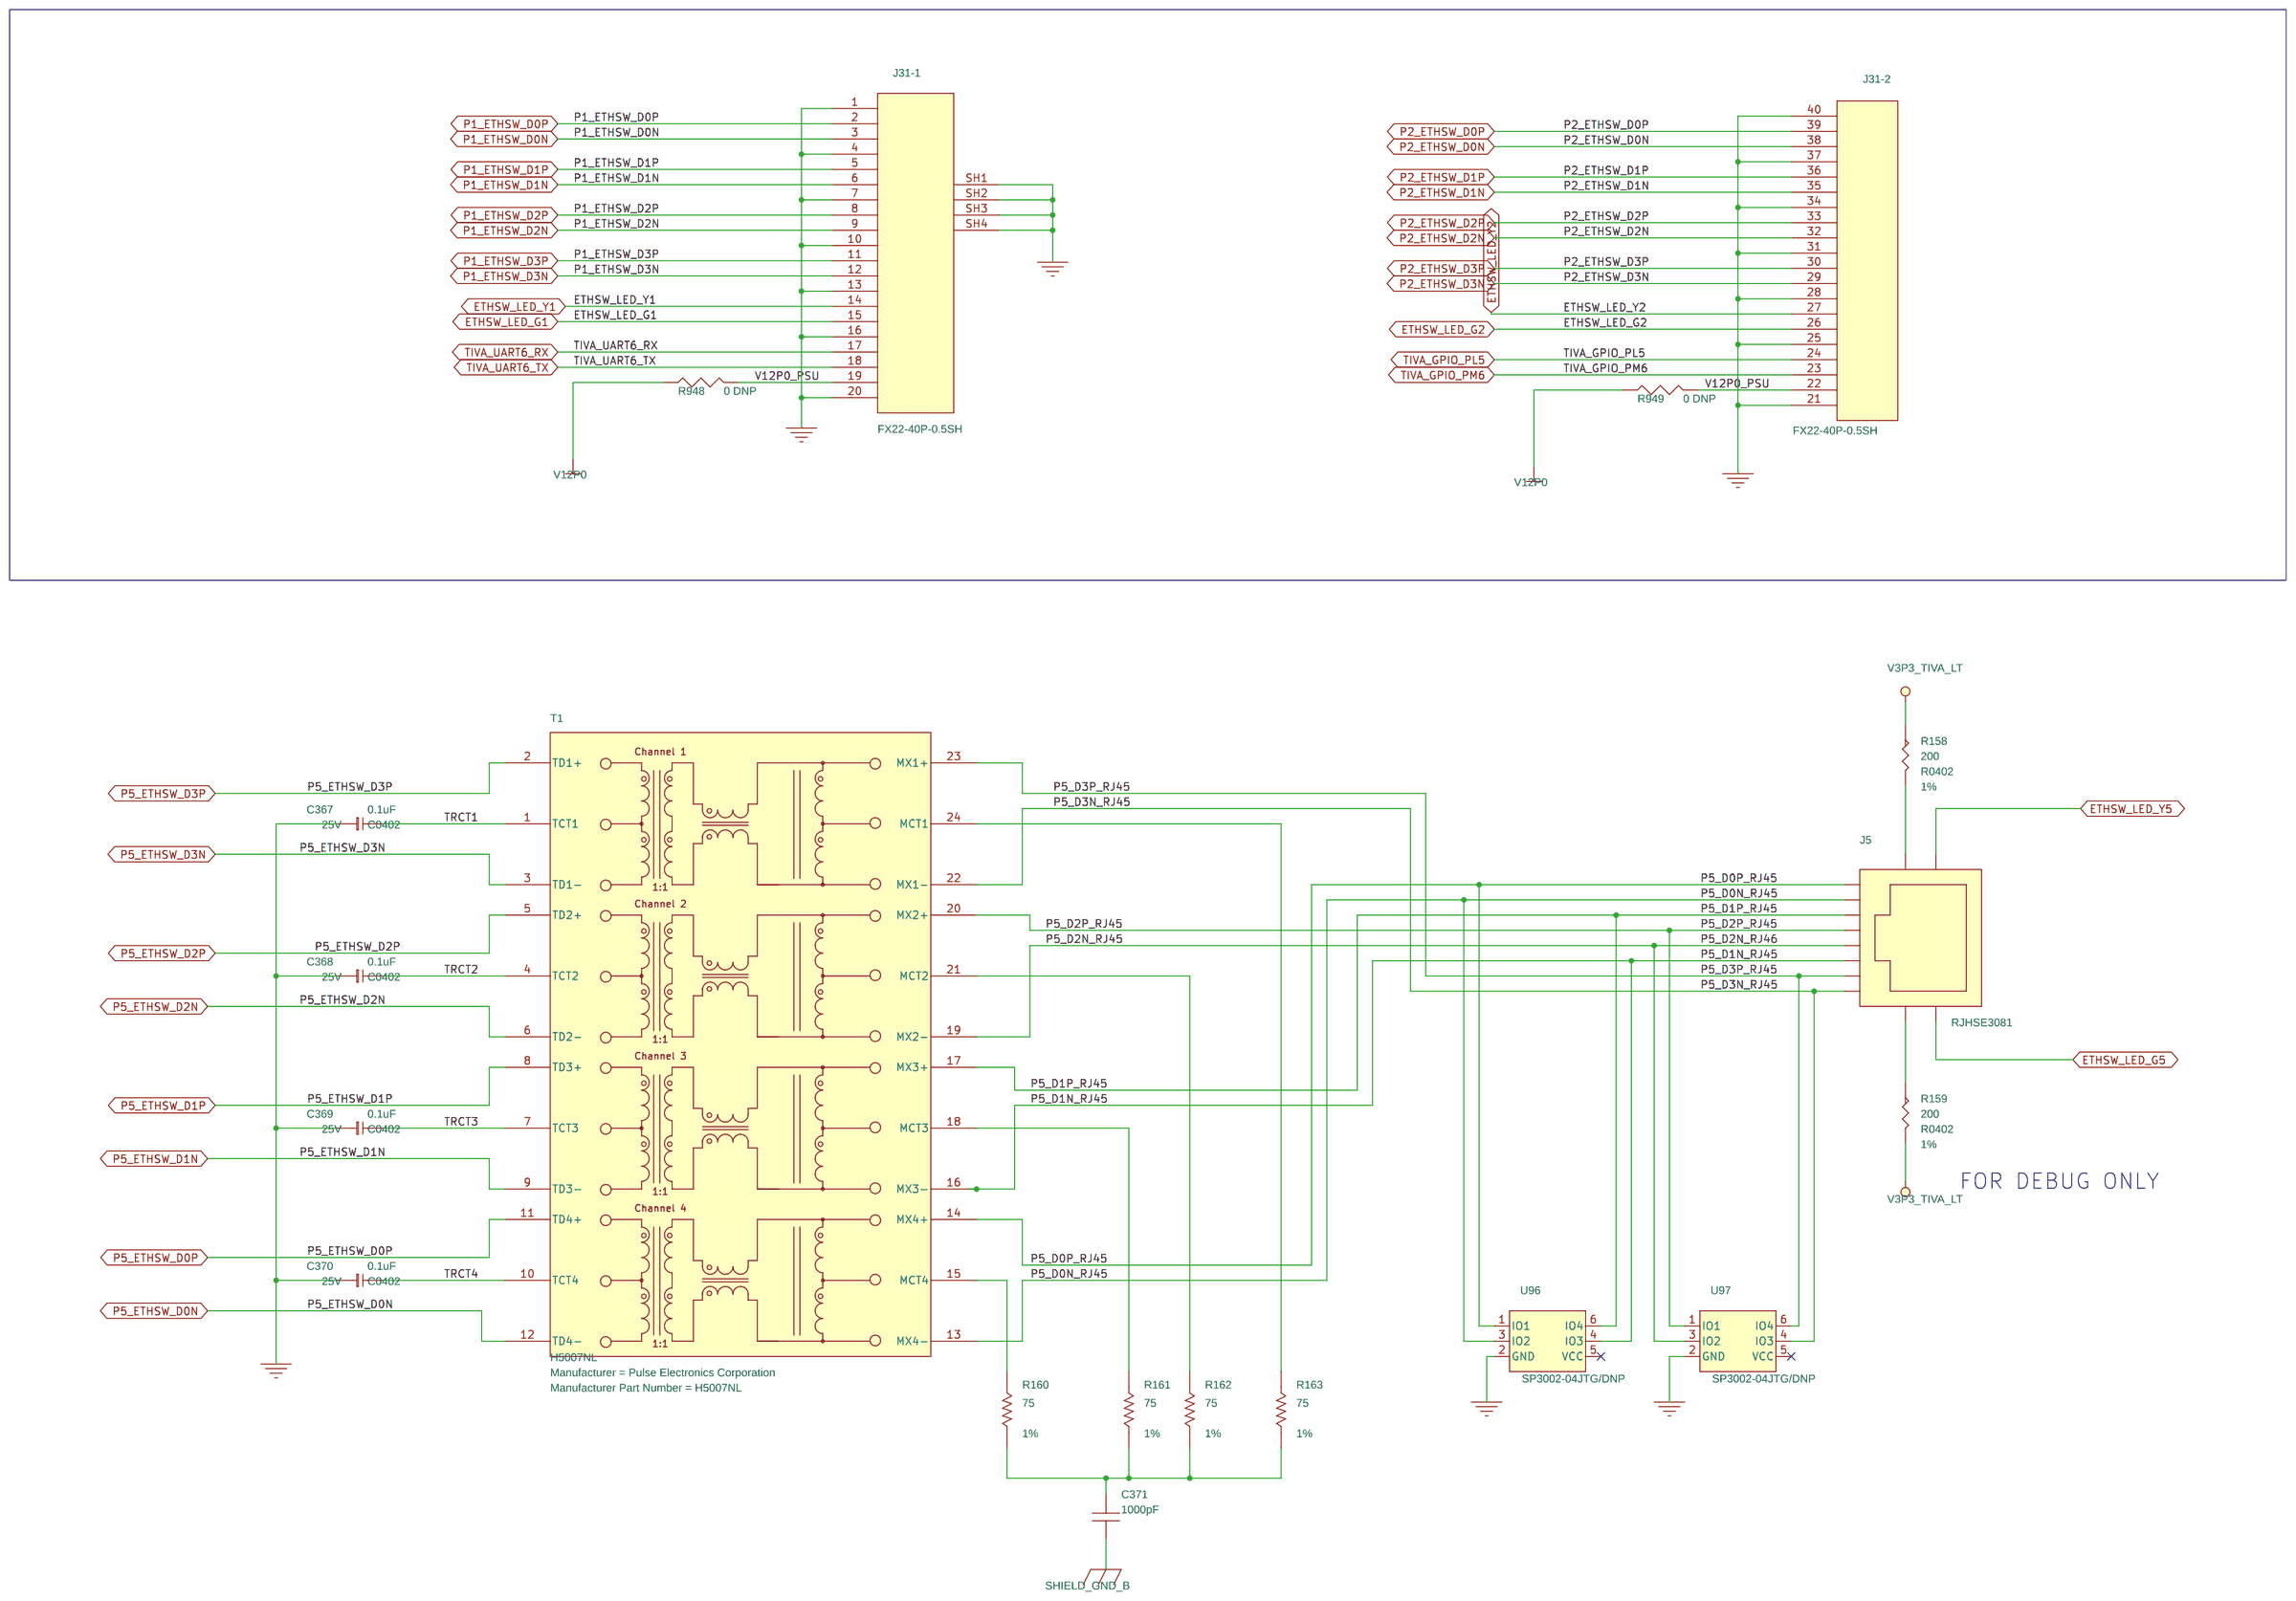
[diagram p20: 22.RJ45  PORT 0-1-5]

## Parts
sheet 13.CN81XX CORE VDD
R107  0  [R0402]
R108  0  [R0402]
R109  0  [R0402]
R110  0  [R0402]
U1  CN8130-1500BG676-SCP-PR11-G  [BGA-676]  (sections A,B,C,D,E,F,G,H,I,J,K)
sheet 15.CN81XX QLM & USB SUPPLY
C125  0.1uF  [C0402]
C126  10uF  [C0805]
C127  1uF  [C0402]
C128  0.1uF  [C0402]
C129  1uF  [C0402]
C130  0.1uF  [C0402]
C131  0.1uF  [C0402]
C132  0.1uF  [C0402]
C133  1uF  [C0402]
C134  10uF  [C0805]
C135  0.1uF  [C0402]
C136  0.1uF  [C0402]
C137  1uF  [C0402]
C138  0.1uF  [C0402]
C139  0.1uF  [C0402]
C140  0.1uF  [C0402]
C141  0.1uF  [C0402]
C142  1uF  [C0402]
C143  0.1uF  [C0402]
C144  0.1uF  [C0402]
C145  10uF  [C0805]
C146  0.1uF  [C0402]
C147  1uF  [C0402]
C148  0.1uF  [C0402]
C149  10uF  [C0805]
C150  10uF  [C0805]
C151  1uF  [C0402]
C152  0.1uF  [C0402]
C153  0.1uF  [C0402]
C154  1uF  [C0402]
C155  10uF  [C0805]
C156  0.1uF  [C0402]
C157  0.1uF  [C0402]
C158  10uF  [C0805]
C159  1uF  [C0402]
C160  0.1uF  [C0402]
C161  0.1uF  [C0402]
C162  0.1uF  [C0402]
C163  0.1uF  [C0402]
C164  1uF  [C0402]
C165  10uF  [C0805]
C166  0.1uF  [C0402]
C167  0.1uF  [C0402]
C168  10uF  [C0805]
C169  1uF  [C0402]
C170  0.1uF  [C0402]
C171  1uF  [C0402]
C172  0.1uF  [C0402]
C173  0.1uF  [C0402]
C174  0.1uF  [C0402]
C175  1uF  [C0402]
C176  10uF  [C0805]
C177  0.1uF  [C0402]
C178  0.1uF  [C0402]
C179  10uF  [C0805]
C180  1uF  [C0402]
C181  0.1uF  [C0402]
C182  0.1uF  [C0402]
C183  0.1uF  [C0402]
C184  0.1uF  [C0402]
C185  1uF  [C0402]
C186  10uF  [C0805]
C187  0.1uF  [C0402]
C188  0.1uF  [C0402]
C189  10uF  [C0805]
C190  1uF  [C0402]
C191  0.1uF  [C0402]
C192  1uF  [C0402]
C193  0.1uF  [C0402]
C194  0.1uF  [C0402]
C195  0.1uF  [C0402]
C196  1uF  [C0402]
C197  10uF  [C0805]
C198  0.1uF  [C0402]
C199  0.1uF  [C0402]
C200  10uF  [C0805]
C201  1uF  [C0402]
C202  0.1uF  [C0402]
C203  0.1uF  [C0402]
C204  0.1uF  [C0402]
C205  0.1uF  [C0402]
C206  1uF  [C0402]
C207  10uF  [C0805]
C208  0.1uF  [C0402]
C209  0.1uF  [C0402]
C210  10uF  [C0805]
C211  1uF  [C0402]
C212  0.1uF  [C0402]
C213  1uF  [C0402]
C214  0.1uF  [C0402]
L10  120R,100MHz,2A  [L0402]
L11  120R,100MHz,2A  [L0402]
L12  120R,100MHz,2A  [L0402]
L13  120R,100MHz,2A  [L0402]
L14  120R,100MHz,2A  [L0402]
L15  120R,100MHz,2A  [L0402]
L16  120R,100MHz,2A  [L0402]
L17  120R,100MHz,2A  [L0402]
L18  120R,100MHz,2A  [L0402]
L19  120R,100MHz,2A  [L0402]
L20  120R,100MHz,2A  [L0402]
L21  120R,100MHz,2A  [L0402]
L22  120R,100MHz,2A  [L0402]
L23  120R,100MHz,2A  [L0402]
L24  120R,100MHz,2A  [L0402]
L25  120R,100MHz,2A  [L0402]
L26  120R,100MHz,2A  [L0402]
R114  49.9  [R0402]
sheet 16.CN81XX GND
R115  0  [R0402]
sheet 17.CN81XX CORE & DDR DECOUPLING
C219  330uF  [CT7343]
C220  330uF  [CT7343]
C221  330uF  [CT7343]
C222  330uF  [CT7343]
C223  330uF  [CT7343]
C234  100uF  [C1206]
C235  100uF  [C1206]
C236  100uF  [C1206]
C237  100uF  [C1206]
C238  100uF  [C1206]
C239  100uF  [C1206]
C240  100uF  [C1206]
C241  100uF  [C1206]
C242  22uF  [C0805_DUT]
C243  22uF  [C0805_DUT]
C244  22uF  [C0805_DUT]
C245  22uF  [C0805_DUT]
C246  22uF  [C0805_DUT]
C247  22uF  [C0805_DUT]
C248  22uF  [C0805_DUT]
C249  1uF  [C0402]
C250  1uF  [C0402]
C251  1uF  [C0402]
C252  1uF  [C0402]
C253  1uF  [C0402]
C254  1uF  [C0402]
C255  1uF  [C0402]
C256  1uF  [C0402]
C257  1uF  [C0402]
C258  1uF  [C0402]
C259  1uF  [C0402]
C260  1uF  [C0402]
C261  1uF  [C0402]
C262  1uF  [C0402]
C263  1uF  [C0402]
C264  0.1uF  [C0402]
C265  0.1uF  [C0402]
C266  0.1uF  [C0402]
C267  0.1uF  [C0402]
C268  0.1uF  [C0402]
C269  0.1uF  [C0402]
C270  0.1uF  [C0402]
C271  0.1uF  [C0402]
C272  0.1uF  [C0402]
C273  0.1uF  [C0402]
C274  0.1uF  [C0402]
C275  0.1uF  [C0402]
C276  0.1uF  [C0402]
C277  330uF  [CT7343]
C278  330uF  [CT7343]
C279  100uF  [C1206]
C280  100uF  [C1206]
C281  100uF  [C1206]
C282  100uF  [C1206]
C283  22uF  [C0805]
C284  22uF  [C0805]
C285  22uF  [C0805]
C286  22uF  [C0805]
C287  1uF  [C0402]
C288  1uF  [C0402]
C289  1uF  [C0402]
C290  1uF  [C0402]
C291  1uF  [C0402]
C292  1uF  [C0402]
C293  1uF  [C0402]
C294  1uF  [C0402]
C295  1uF  [C0402]
C296  1uF  [C0402]
C297  1uF  [C0402]
C298  1uF  [C0402]
C299  1uF  [C0402]
C300  1uF  [C0402]
C301  1uF  [C0402]
C302  1uF  [C0402]
C303  1uF  [C0402]
C304  1uF  [C0402]
C305  0.1uF  [C0402]
C306  0.1uF  [C0402]
C307  0.1uF  [C0402]
C308  0.1uF  [C0402]
C309  0.1uF  [C0402]
C310  0.1uF  [C0402]
C311  0.1uF  [C0402]
C312  0.1uF  [C0402]
C313  0.1uF  [C0402]
C314  0.1uF  [C0402]
C315  0.1uF  [C0402]
C316  0.1uF  [C0402]
C317  0.1uF  [C0402]
C318  0.1uF  [C0402]
C319  0.1uF  [C0402]
C320  0.1uF  [C0402]
C321  0.1uF  [C0402]
C322  0.1uF  [C0402]
C851  0.1uF  [C0402-BGA]
C852  0.1uF  [C0402-BGA]
C853  0.1uF  [C0402-BGA]
C854  0.1uF  [C0402-BGA]
C855  0.1uF  [C0402-BGA]
C856  0.1uF  [C0402-BGA]
C857  0.1uF  [C0402-BGA]
C858  0.1uF  [C0402-BGA]
C859  0.1uF  [C0402-BGA]
C860  0.1uF  [C0402-BGA]
C861  0.1uF  [C0402-BGA]
C862  0.1uF  [C0402-BGA]
C863  0.1uF  [C0402-BGA]
C864  1uF  [C0402-BGA]
C865  1uF  [C0402-BGA]
C866  1uF  [C0402-BGA]
C867  1uF  [C0402-BGA]
C868  1uF  [C0402-BGA]
C869  1uF  [C0402-BGA]
C870  1uF  [C0402-BGA]
C871  1uF  [C0402-BGA]
C872  1uF  [C0402-BGA]
C873  1uF  [C0402-BGA]
C874  1uF  [C0402-BGA]
C875  1uF  [C0402-BGA]
C876  1uF  [C0402-BGA]
C877  1uF  [C0402-BGA]
C878  1uF  [C0402-BGA]
sheet 18.CN81XX STRAPPING
R116  2K/DNP  [R0402]
R117  2K/DNP  [R0402]
R787  4.7K  [R0402]
R788  4.7K  [R0402]
R789  4.7K  [R0402]
R790  4.7K  [R0402]
R791  4.7K  [R0402]
R792  4.7K  [R0402]
R793  4.7K  [R0402]
R794  4.7K  [R0402]
R795  4.7K  [R0402]
R796  4.7K  [R0402]
R797  4.7K  [R0402]
R798  4.7K  [R0402]
R799  4.7K/DNP  [R0402]
R800  4.7K  [R0402]
R801  4.7K  [R0402]
R802  4.7K/dnp  [R0402]
R803  4.7K  [R0402]
R804  4.7K/dnp  [R0402]
R805  4.7K/dnp  [R0402]
R806  4.7K  [R0402]
R807  4.7K/dnp  [R0402]
R808  4.7K  [R0402]
sheet 19.RTC & THERMAL SENSORS
BT1  CR-1220/HFN  [BAT_CR-1220HFN]
C323  0.1uF  [C0402]
C324  0.1uF  [C0402]
C325  12pF/DNP  [C0402]
C326  12pF/DNP  [C0402]
C327  0.1uF  [C0402]
C328  470pF/dnp  [C0603]
C329  0.01uF/DNP  [C0402]
D7  BAT54C/SOT  [SOT-23-3]
FB2  120@100MHZ  [L0402]
FB3  120@100MHZ  [L0402]
J3  22-23-2021/dnp  [HDR_2X2_SHD]
J4  22-23-2031/dnp  [JUMPER3_FAN]
Q7  NDT3055L/DNP  [SOT_223]
Q8  NDT3055L/dnp  [SOT_223]
R118  10K  [R0402]
R119  4.7K  [R0402]
R120  10K  [R0402]
R121  10K  [R0402]
R122  0  [R0402]
R123  0  [R0402]
R124  10K/dnp  [R0402]
R125  10K/dnp  [R0402]
R126  10K/dnp  [R0402]
R127  10K/dnp  [R0402]
R130  0  [R0402]
R131  0  [R0402]
R134  0/dnp  [R1206]
R135  0/dnp  [R1206]
R136  0/dnp  [R1206]
R137  0/dnp  [R1206]
R138  0/dnp  [R0402]
R139  10/dnp  [R0805]
R140  0/DNP  [R0402]
TP6  TEST POINT  [TP_SMD]
U5  DS1337  [SOIC-8]
U6  24LC256-I/MS  [SOIC127P600X175-8N_ON-SEMI]
U7  EMC2101-ACZT-TR  [soic8_1o27mm_6x4o9_h1o75_ti]
X2  32.768kHz  [XTAL205X120X60N]
sheet 20.ETHERNET SWITCH
C330  12pF  [C0402]
C331  12pF  [C0402]
C844  0.1uF  [C0402]
C845  0.1uF  [C0402]
R141  22  [R0402]
R142  22  [R0402]
R143  22  [R0402]
R144  22  [R0402]
R145  22  [R0402]
R146  22  [R0402]
R147  10K  [R0402]
R148  10K  [R0402]
R149  6.04K  [R0402]
R150  1K  [R0402]
R151  1K  [R0402]
R768  10K  [R0402]
R769  191  [R0402]
R771  22  [R0402]
R772  22  [R0402]
R773  22/DNP  [R0402]
R774  0  [R0402]
R775  0  [R0402]
R917  1K/dnp  [R0402]
X3  25MHZCRYSTAL  [SMY_FA128]
sheet 21.ETHERNET SWITCH POWER
C332  10UF  [C1206]
C333  0.1uF  [C0402]
C334  0.1uF  [C0402]
C335  0.1uF  [C0402]
C336  0.1uF  [C0402]
C337  0.1uF  [C0402]
C338  0.1uF  [C0402]
C339  0.1uF  [C0402]
C340  10UF  [C1206]
C341  0.1uF  [C0402]
C342  0.1uF  [C0402]
C343  0.1uF  [C0402]
C344  0.1uF  [C0402]
C345  0.1uF  [C0402]
C346  0.1uF  [C0402]
C347  0.1uF  [C0402]
C348  0.1uF  [C0402]
C349  0.1uF  [C0402]
C350  10uF  [C0805]
C351  10UF  [C1206]
C352  0.1uF  [C0402]
C353  0.1uF  [C0402]
C354  0.1uF  [C0402]
C355  0.1uF  [C0402]
C356  0.1uF  [C0402]
C357  0.1uF  [C0402]
C358  0.1uF  [C0402]
C359  0.1uF  [C0402]
C360  22uF  [C0805]
C361  10UF  [C1206]
C362  0.1uF  [C0402]
C363  0.1uF  [C0402]
C364  0.1uF  [C0402]
C365  10uF  [C0805]
C366  22uF  [C0805]
C846  0.1uF  [C0402]
C847  0.1uF  [C0402]
D38  LED  [LED_LTST-C190]
FB4  120E  [INDC1608X95M]
FB5  120E  [INDC1608X95M]
L27  2.2uH  [IND3838X190]
L28  2.2uH  [IND3838X190]
R152  10K  [R0402]
R153  200K  [R0402]
R154  200K  [R0402]
R155  200K  [R0402]
R156  10K  [R0402]
R157  63.4K  [R0402]
R877  0  [R1812]
R878  0  [R1812]
R890  200  [R0402]
TP7  TP_PWR  [TP_TH_40MIL]
TP8  TP_PWR  [TP_TH_40MIL]
TP9  TP_PWR  [TP_TH_40MIL]
TP10  TP_PWR  [TP_TH_40MIL]
U9  KSZ9567S  [KSZ9897S]  (sections -1,-2)
U10  MP2162AGQH  [QFN8]
U11  MP2162AGQH  [QFN8]
sheet 22.RJ45  PORT 0-1-5
C367  0.1uF  [C0402]
C368  0.1uF  [C0402]
C369  0.1uF  [C0402]
C370  0.1uF  [C0402]
C371  1000pF  [C1812]
J5  RJHSE3081  [RJHSE3081]
J31  FX22-40P-0.5SH  [HIROSE_FX22-40S-0P5SH]  (sections -1,-2)
R158  200  [R0402]
R159  200  [R0402]
R160  75  [R0603]
R161  75  [R0603]
R162  75  [R0603]
R163  75  [R0603]
R948  0 DNP  [R1812]
R949  0 DNP  [R1812]
T1  H5007NL  [H5007NL]
U96  SP3002-04JTG/DNP  [SC70-6]
U97  SP3002-04JTG/DNP  [SC70-6]

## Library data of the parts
R107 R110 = R: RES SMD 0.0OHM JUMPER 1/16W 0402; MFG: Panasonic; MFG_PN: ERJ-2GE0R00X; Manufacturer: VISHAY DALE; Manufacturer Part Number: CRCW04020000Z0ED; PART_NUMBER: ERJ-2RKF1000X
R108 R109 = RES_0: RES SMD 0.0OHM JUMPER 1/16W 0402; MFG: Panasonic; MFG_PN: ERJ-2GE0R00X; Manufacturer: VISHAY DALE; Manufacturer Part Number: CRCW04020000Z0ED; PART_NUMBER: PAC_RES_02050
U1 = CN81XX_List_V0_3.60: Manufacturer: CAVIUM
C125 C128 C130-C132 C135 C136 C138-C141 C143 C144 C146 C148 C152 C153 C156 C157 C160-C163 C166 C167 C170 C172-C174 C177 C178 C181-C184 C187 C188 C191 C193-C195 C198 C199 C202-C205 C208 C209 C212 C214 C264-C276 C305-C319 C321-C323 C844 C845 C851-C863 = CAP_NONPOL: CAP CER 0.1UF 25V 10% X7R 0402; MFG: Murata; MFG_PN: GRM155R71C104KA88D; Manufacturer: MURATA; Manufacturer Part Number: GRM155R71C104KA88D; Tolerance: ±10%; Voltage: 25V
C126 C134 C145 C149 C150 C155 C158 C165 C168 C176 C179 C186 C189 C197 C200 C207 C210 = CAP_NONPOL: CAP CER 10UF 16V X5R 0805; MFG: MURATA; MFG_PN: GRM21BR61C106KE15K; Manufacturer: MURATA; Manufacturer Part Number: GRM21BR61C106KE15K; Tolerance: ±10%; Voltage: 16V
C127 C129 C133 C137 C142 C147 C151 C154 C159 C164 C169 C171 C175 C180 C185 C190 C192 C196 C201 C206 C211 C213 C249-C263 C287-C304 C864-C878 = CAP_NONPOL: CAP CER 1UF 4V X7R 0402; MFG: Murata; MFG_PN: GRM155R70G105KA12D; Manufacturer: MURATA; Manufacturer Part Number: GRM155R70G105KA12D; Tolerance: ±10%; Voltage: 4V
L10-L26 = FERRITE_BEAD: FERRITE BEAD 120 OHM 0402 1LN; Manufacturer: MURATA; Manufacturer Part Number: BLM15PX121SN1D
R114 = RESISTOR_1: RES SMD 49.9 OHM 1% 1/10W 0402; Manufacturer: Panasonic; Manufacturer Part Number: ERJ-2RKF49R9X; Tolerance: 1%; Wattage: 1/16W
R115 R122 R123 R130 R140 = res_0402_0R0_0.1W_Jmpr_smd: RES SMD 0.0OHM JUMPER 1/16W 0402; Manufacturer: VISHAY DALE; Manufacturer Part Number: CRCW04020000Z0ED; Tolerance: jmpr
C219-C223 C277 C278 = CAP_POL_1: CAP TANT POLY 330UF 6.3V 2917; Manufacturer: Panasonic; Manufacturer Part Number: 6TPF330M9L; Tolerance: 20%; Voltage: 6.3V
C234-C241 C279-C282 = CAP_NONPOL: CAP CER 100UF 6.3V X5R 1206; Manufacturer: MURATA; Manufacturer Part Number: GRM31CR60J107ME39K; Tolerance: 20%; Voltage: 6.3V
C242-C248 = CAP_NONPOL: CAP CER 22UF 6.3V X5R 0805; MFG: Murata; MFG_PN: GRM21BR60J226ME39L; Manufacturer: MURATA; Manufacturer Part Number: GRM21BR60J226ME39L; Tolerance: ±20%; Voltage: 6.3V
C283-C286 = CAP_NONPOL: CAP CER 22UF 25V X5R 0805; MFG: Murata; MFG_PN: GRM21BR61E226ME44L; Manufacturer: MURATA; Manufacturer Part Number: GRM21BR61E226ME44L; Tolerance: ±20%; Voltage: 25V
C320 = CAP_NONPOL: CAP CER 0.1UF 25V 10% X7R 0402; MFG: Murata; MFG_PN: GRM155R71C104KA88D; Manufacturer: MURATA; Manufacturer Part Number: GRM155R71C104KA88D; Tolerance: ?%; Voltage: 25V
R116 R117 = RESISTOR_1: RES SMD 2K OHM 5% 1/10W 0402; MFG: Panasonic; MFG_PN: ERJ-2GEJ202X; Manufacturer: Panasonic; Manufacturer Part Number: ERJ-2GEJ202X; Tolerance: ±5%; Wattage: 1/16W
R787-R808 = RESISTOR_1: RES 4.7K OHM 1/10W 5% 0402 SMD; Manufacturer: Panasonic; Manufacturer Part Number: ERJ-2GEJ472X; Tolerance: ?%; Wattage: 1/16W
BT1 = BATTERY: BATTERY LITHIUM 3V COIN 16MM; ICA_MFR_NAME: PANASONIC CORP; ICA_PARTNUM: $$1651322$$CR1220; Manufacturer: Panasonic - BSG; Manufacturer Part Number: BR-1632/V1AN; Part Number: BR-1632/V1AN
C324 C327 = cap_0402_0.1uF_16V_10%_X7R: CAP CER 0.1UF 25V 10% X7R 0402; Manufacturer: MURATA; Manufacturer Part Number: GRM155R71C104KA88D; Voltage: 25V
C325 C326 = CAP_NONPOL: CAP CER 12PF 50V NP0 0402; MFG: MURATA; MFG_PN: GRM1555C1E120JA01D; Manufacturer: Kemet; Manufacturer Part Number: CBR04C120F5GAC; Tolerance: ±5%; Voltage: 50V
C328 = cap_0603_470pF_100V_5%_X7R
C329 = cap_0402_0.01uF_16V_10%_X7R: CAP  0402 CER 0.01uF 16V 10%  X7R; Manufacturer: Murata; Manufacturer Part Number: GRM155R71C103KA01J; Voltage: 16V
D7 = BAT54C_SOT_0: DIODE ARRAY SCHOTTKY 30V SOT233; Manufacturer: Diodes Incorporated; Manufacturer Part Number: BAT54CTA
FB2 FB3 = fer_120_1.5A_BLM15EG121SN1D_sm: Manufacturer: MURATA; Manufacturer Part Number: BLM15EG121SN1D
J3 = two_pin_fan_hdr_0022232021: Manufacturer: MOLEX; Manufacturer Part Number: 22-23-2021
J4 = 22-23-2031: MFG: Molex; Manufacturer: MOLEX
Q7 = MOSFET_N_2V_60V_4A_0.1W_sm: Manufacturer: ON Semiconductor; Manufacturer Part Number: NDT3055LTR-ND
Q8 = MOSFET_N_2V_60V_4A_1.1W_sm: Manufacturer: ON Semiconductor; Manufacturer Part Number: NDT3055LTR-ND
R118 R120 R121 = RESISTOR_1: RES SMD 10K OHM 5% 1/16W 0402; MFG: VISHAY DALE; MFG_PN: CRCW040210K0JNED; Manufacturer: VISHAY DALE; Manufacturer Part Number: CRCW040210K0JNED; Tolerance: ±5%; Wattage: 1/16W
R119 = res_0402_4K7_0.063W_1%_smd: RES 4.7K OHM 1/10W 5% 0402 SMD; MFG: Panasonic; MFG_PN: ERJ-2GEJ472X; Manufacturer: Panasonic; Manufacturer Part Number: ERJ-2GEJ472X; Tolerance: 5%
R124-R127 = res_0402_10K0_0.063W_1%_smd
R131 R138 = res_0402_0R0_0.1W_Jmpr_smd: RES SMD 0.0OHM JUMPER 1/16W 0402; MFG: Panasonic; Manufacturer: VISHAY DALE; Manufacturer Part Number: CRCW04020000Z0ED; Tolerance: jmpr
R134 R135 R137 = res_1206_0R0_0.25W_smd: RES SMD 0.0OHM JUMPER 1/16W 0402; Manufacturer: VISHAY DALE; Manufacturer Part Number: CRCW04020000Z0ED
R136 = res_1206_0R0_0.25W_smd: RES SMD 0.0OHM JUMPER 1/16W 0402; Manufacturer: VISHAY DALE; Manufacturer Part Number: RC1206JR-070RL
R139 = res_0805_10R0_0.1W_1%_smd
TP6 = TEST_POINT
U5 = ISL12057-RTC: IC RTC CLK/CALENDAR I2C 8-SOIC; Manufacturer: DALLAS/MAXIM; Manufacturer Part Number: DS1337S+
U6 = IC_EEPROM_256Kb_400KHz_8MSOP: Manufacturer: Microchip
U7 = IC_FAN_CONTR_TEMP_SENS: Manufacturer: Microchip Technology
X2 = ABS25_32_768KHZ_T_0: CRYSTAL 32.7680KHZ 12.5PF SMD; Manufacturer: EPSON; Manufacturer Part Number: FC-12M 32.7680KA-A5
C330 C331 = CAP_CER_0.1UF_10V_10%_X5R_0402: CAP CER 12PF 50V NP0 0402; MATERIAL: NPO; Manufacturer: Kemet; Manufacturer Part Number: CBR04C120F5GAC; PART_NUMBER: 0.1UF; Part Number: CBR04C120F5GAC; TOLERANCE: 1%; VOLTAGE: 50V
R141-R146 R771 R772 = RESISTOR_1: RES SMD 22 OHM 1% 1/16W 0402; Manufacturer: VISHAY DALE; Manufacturer Part Number: CRCW040222R0FKED; Tolerance: ±1%; Wattage: 1/16W
R147 R148 R768 = RESISTOR_1: RES SMD 10K OHM 1% 1/16W 0402; Manufacturer: VISHAY DALE; Manufacturer Part Number: CRCW040210K0FKED; Tolerance: ±1%; Wattage: 1/16W
R149 = RESISTOR_1: RES SMD 6.04K OHM 1% 1/16W 0402; Manufacturer: Yageo; Manufacturer Part Number: RC0402FR-076K04L; Tolerance: 1%; Wattage: 1/16W
R150 R151 R917 = RESISTOR_1: RES SMD 1K OHM 5% 1/16W 0402; Manufacturer: VISHAY DALE; Manufacturer Part Number: CRCW04021K00JNED; Tolerance: ±5%; Wattage: 1/10W
R769 = RESISTOR_1: RES SMD 191ohm  1% 1/16W 0402; Manufacturer: VISHAY DALE; Manufacturer Part Number: CRCW0402191RFKED; Tolerance: 1%; Wattage: 1/16W
R773 = RESISTOR_1: RES SMD 22 OHM 1% 1/16W 0402; Manufacturer: VISHAY DALE; Manufacturer Part Number: CRCW040222R0FKED; Tolerance: ?%; Wattage: 1/16W
R774 R775 = RES_0402: RES SMD 0.0OHM JUMPER 1/16W 0402; Manufacturer: VISHAY DALE; Manufacturer Part Number: CRCW04020000Z0ED
X3 = XTAL_4P_25: CRYSTAL 25.0000MHZ 6PF SMD; Manufacturer: EPSON; Manufacturer Part Number: FA-128 25.0MHZ6PF30PPM; Part Number: FA-128 25.0MHZ6PF30PPM
C332 C340 C351 C361 = CAP_CER_0.1UF_10V_10%_X5R_0402: CAP CER 10UF 25V 10% X7R 1206; MATERIAL: X7R; Manufacturer: Taiyo Yuden; PART_NUMBER: 0.1UF; Part Number: TMK316B7106KL-TD; TOLERANCE: 10%; VOLTAGE: 25V
C333-C339 C341-C349 C352-C359 C362-C364 C846 C847 = CAP_CER_0.1UF_10V_10%_X5R_0402: CAP CER 0.1UF 25V 10% X7R 0402; MATERIAL: X7R; Manufacturer: MURATA; Manufacturer Part Number: GRM155R71C104KA88D; PART_NUMBER: 0.1UF; Part Number: C1005X7R1E104K050BB; TOLERANCE: 10%; VOLTAGE: 25V
C350 C365 = CAP_NONPOL: CAP CER 10UF 16V X5R 0805; Manufacturer: MURATA; Manufacturer Part Number: GRM21BR61C106KE15K; Tolerance: ±10%; Voltage: 16V
C360 C366 = CAP_NONPOL: CAP CER 22UF 25V X5R 0805; Manufacturer: MURATA; Manufacturer Part Number: GRM21BR61E226ME44L; Tolerance: ±20%; Voltage: 25V
D38 = LED_wp117: LED GREEN DIFFUSED 0603 SMD; Manufacturer: Lumex; Manufacturer Part Number: SML-LX0603GW-TR; Part Number: LTST-C190KGKT
FB4 FB5 = FB_0: FERRITE CHIP 120 OHM 2000MA 0603; Manufacturer: Murata Electronics North America; Manufacturer Part Number: BLM18PG121SN1D; Part Number: BLM18PG121SN1D
L27 L28 = INDUCTOR_0: FIXED IND 2.2UH 3A 45 MOHM SMD; Manufacturer: Vishay; Manufacturer Part Number: IFSC1515AHER2R2M01
R152 R156 = RESISTOR_1: RES SMD 10K OHM 5% 1/16W 0402; Manufacturer: VISHAY DALE; Manufacturer Part Number: CRCW040210K0JNED; Tolerance: ±5%; Wattage: 1/16W
R153-R155 = RESISTOR_1: RES SMD 200K OHM 1% 1/16W 0402; Manufacturer: VISHAY DALE; Manufacturer Part Number: CRCW0402200KFKED; Tolerance: ±1%; Wattage: 1/16W
R157 = RESISTOR_1: RES SMD 63.4K OHM 1% 1/16W 0402; Manufacturer: VISHAY DALE; Manufacturer Part Number: CRCW040263K4FKED; Tolerance: 1%; Wattage: 1/16W
R877 R878 R948 R949 = R: RES SMD 0 OHM 1W 1812 WIDE; Manufacturer: Vishay Dale; Manufacturer Part Number: RCL12180000Z0EK
R158 R159 R890 = RESISTOR_1: RES SMD 200 OHM 1% 1/16W 0402; Manufacturer: VISHAY DALE; Manufacturer Part Number: CRCW0402200RFKED; Tolerance: 1%; Wattage: 1/16W
TP7-TP10 = T_POINT_R
U9 = KSZ9567S: 7-Port Gigabit Ethernet AVB Switch; Manufacturer: MichoChip; Manufacturer Part Number: KSZ9567STXI; Part Number: KSZ9567STXI
U10 U11 = MP2162: MP2162A, 2A, 6V, 1.5Mhz; Manufacturer: MPS
C367-C370 = CAP_NONPOL: CAP CER 0.1UF 25V 10% X7R 0402; Manufacturer: MURATA; Manufacturer Part Number: GRM155R71C104KA88D; Tolerance: ±10%; Voltage: 25V
C371 = CAP: CAP CER 1000PF 3KV X7R 1812; Assembly Option: LOAD; Manufacturer: KEMET; Manufacturer PN: C1812C102KHRACTU; Manufacturer Part Number: C1812C102KHRACTU; PART_NUMBER: PAC_CAP_02425; Tolerance: 10%; Voltage: 3KV
J5 = MRJ-5480-01: Manufacturer: Amphenol Commercial Products; Manufacturer Part Number: RJHSE-3081
J31 = FX18-40S-0_4.8SH: CONN HDR 0.5MM 40POS RA SMD
R160-R163 = RES_0: RES SMD 75 OHM 1% 1/8W 0603; Assembly Option: LOAD; Manufacturer: Stackpole Electronics Inc.; Manufacturer PN: RNCP0603FTD75R0; Manufacturer Part Number: RNCP0603FTD75R0; PART_NUMBER: PAC_RES_01894; Tolerance: 1%
T1 = MAGNETICS_H5007NL: MODULE SINGLE GIGABIT LAN 24SOIC; Manufacturer: Pulse Electronics Corporation
U96 U97 = SP3002-04JTG

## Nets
3V3_SENSE_N: R115.1 ; also on sheet 52
GND: BT1.2(-) C125.2 C126.2 C127.2 C128.2 C129.2 C130.2 C131.2 C132.2 C133.2 C134.2 C135.2 C136.2 C137.2 C138.2 C139.2 C140.2 C141.2 C142.2 C143.2 C144.2 C145.2 C146.2 C147.2 C148.2 C149.2 C150.2 C151.2 C152.2 C153.2 C154.2 C155.2 C156.2 C157.2 C158.2 C159.2 C160.2 C161.2 C162.2 C163.2 C164.2 C165.2 C166.2 C167.2 C168.2 C169.2 C170.2 C171.2 C172.2 C173.2 C174.2 C175.2 C176.2 C177.2 C178.2 C179.2 C180.2 C181.2 C182.2 C183.2 C184.2 C185.2 C186.2 C187.2 C188.2 C189.2 C190.2 C191.2 C192.2 C193.2 C194.2 C195.2 C196.2 C197.2 C198.2 C199.2 C200.2 C201.2 C202.2 C203.2 C204.2 C205.2 C206.2 C207.2 C208.2 C209.2 C210.2 C211.2 C212.2 C213.2 C214.2 C219.2N C220.2N C221.2N C222.2N C223.2N C234.2 C235.2 C236.2 C237.2 C238.2 C239.2 C240.2 C241.2 C242.2 C243.2 C244.2 C245.2 C246.2 C247.2 C248.2 C249.2 C250.2 C251.2 C252.2 C253.2 C254.2 C255.2 C256.2 C257.2 C258.2 C259.2 C260.2 C261.2 C262.2 C263.2 C264.2 C265.2 C266.2 C267.2 C268.2 C269.2 C270.2 C271.2 C272.2 C273.2 C274.2 C275.2 C276.2 C277.2N C278.2N C279.2 C280.2 C281.2 C282.2 C283.2 C284.2 C285.2 C286.2 C287.2 C288.2 C289.2 C290.2 C291.2 C292.2 C293.2 C294.2 C295.2 C296.2 C297.2 C298.2 C299.2 C300.2 C301.2 C302.2 C303.2 C304.2 C305.2 C306.2 C307.2 C308.2 C309.2 C310.2 C311.2 C312.2 C313.2 C314.2 C315.2 C316.2 C317.2 C318.2 C319.2 C320.2 C321.2 C322.2 C323.2 C324.2 C325.2 C326.2 C327.2 C330.2(B[0]) C331.2(B[0]) C332.2(B[0]) C333.2(B[0]) C334.2(B[0]) C335.2(B[0]) C336.2(B[0]) C337.2(B[0]) C338.2(B[0]) C339.2(B[0]) C340.2(B[0]) C341.2(B[0]) C342.2(B[0]) C343.2(B[0]) C344.2(B[0]) C345.2(B[0]) C346.2(B[0]) C347.2(B[0]) C348.2(B[0]) C349.2(B[0]) C350.2 C351.2(B[0]) C352.2(B[0]) C353.2(B[0]) C354.2(B[0]) C355.2(B[0]) C356.2(B[0]) C357.2(B[0]) C358.2(B[0]) C359.2(B[0]) C360.2 C361.2(B[0]) C362.2(B[0]) C363.2(B[0]) C364.2(B[0]) C365.2 C366.2 C367.2 C368.2 C369.2 C370.2 C846.2(B[0]) C847.2(B[0]) C851.2 C852.2 C853.2 C854.2 C855.2 C856.2 C857.2 C858.2 C859.2 C860.2 C861.2 C862.2 C863.2 C864.2 C865.2 C866.2 C867.2 C868.2 C869.2 C870.2 C871.2 C872.2 C873.2 C874.2 C875.2 C876.2 C877.2 C878.2 D38.K J31.1 J31.4 J31.7 J31.10 J31.13 J31.16 J31.20 J31.21 J31.25 J31.28 J31.31 J31.34 J31.37 J31.40 J31.SH1 J31.SH2 J31.SH3 J31.SH4 R110.2 R114.1 R115.2 R116.1 R117.1 R139.1 R140.1 R147.1 R149.1 R151.1 R154.1 R157.1 R769.1 R787.1 R789.1 R790.1 R791.1 R792.1 R795.1 R796.1 R797.1 R798.2 R800.1 R801.2 R803.2 R805.2 R807.2 R917.1 TP8.1(TP) TP10.1(TP) U1.A1(GND5) U1.A5(GND6) U1.A8(GND7) U1.A11(GND8) U1.A21(GND9) U1.A24(GND10) U1.A26(GND11) U1.AA16(GND174) U1.AA19(GND175) U1.AA21(GND176) U1.AA22(GND177) U1.AA24(GND178) U1.AA25(GND179) U1.AB16(GND180) U1.AB17(GND181) U1.AB18(GND182) U1.AB19(GND183) U1.AB20(GND184) U1.AB21(GND185) U1.AB23(GND186) U1.AB24(GND187) U1.AB26(GND188) U1.AC3(GND189) U1.AC9(GND190) U1.AC21(GND191) U1.AC24(GND192) U1.AD14(GND193) U1.AD18(GND194) U1.AD19(GND195) U1.AD20(GND196) U1.AD21(GND197) U1.AD22(GND198) U1.AD24(GND199) U1.AD25(GND200) U1.AE1(GND201) U1.AE10(GND212) U1.AE18(GND202) U1.AE23(GND203) U1.AE26(GND204) U1.AF2(GND205) U1.AF7(GND1) U1.AF14(GND211) U1.AF18(GND206) U1.AF25(GND207) U1.AF26(GND208) U1.B2(GND12) U1.B14(GND13) U1.B18(GND14) U1.B23(GND15) U1.C1(GND16) U1.C2(GND17) U1.C3(GND18) U1.C4(GND19) U1.C5(GND20) U1.C6(GND21) U1.C8(GND22) U1.C11(GND23) U1.C15(GND4) U1.C19(GND24) U1.C21(GND25) U1.C22(GND26) U1.C23(GND27) U1.C25(GND28) U1.D6(GND29) U1.D13(GND2) U1.D20(GND30) U1.D23(GND31) U1.E15(GND210) U1.E17(GND32) U1.E23(GND33) U1.E24(GND34) U1.E25(GND35) U1.F1(GND36) U1.F2(GND37) U1.F3(GND38) U1.F5(GND39) U1.F6(GND40) U1.F19(GND41) U1.F21(GND42) U1.F22(GND43) U1.F26(GND44) U1.G8(GND45) U1.G13(GND3) U1.G17(GND209) U1.G20(GND46) U1.G25(GND47) U1.H1(GND48) U1.H4(GND49) U1.H7(GND50) U1.H10(GND51) U1.H12(GND52) U1.H14(GND53) U1.H21(GND54) U1.H25(GND55) U1.J3(GND56) U1.J6(GND57) U1.J9(GND58) U1.J11(GND59) U1.J13(GND60) U1.J16(GND213) U1.J22(GND61) U1.J23(GND62) U1.J24(GND63) U1.J25(GND64) U1.J26(GND65) U1.K1(GND66) U1.K3(GND67) U1.K8(GND68) U1.K10(GND69) U1.K12(GND70) U1.K16(GND71) U1.K19(GND72) U1.K21(GND73) U1.K23(GND74) U1.K24(GND75) U1.K26(GND76) U1.L6(GND77) U1.L9(GND78) U1.L11(GND79) U1.L13(GND80) U1.L15(GND81) U1.L16(GND214) U1.L19(GND82) U1.L21(GND83) U1.L24(GND84) U1.M2(GND85) U1.M3(GND86) U1.M5(GND87) U1.M10(GND88) U1.M12(GND89) U1.M14(GND90) U1.M16(GND91) U1.M20(GND92) U1.M21(GND93) U1.M22(GND94) U1.M24(GND95) U1.M25(GND96) U1.N1(GND97) U1.N9(GND98) U1.N11(GND99) U1.N12(GND100) U1.N19(GND102) U1.N21(GND103) U1.N23(GND104) U1.N24(GND105) U1.N26(GND106) U1.P9(GND107) U1.P10(GND108) U1.P13(GND109) U1.P15(GND110) U1.P16(GND111) U1.P19(GND112) U1.P21(GND113) U1.P24(GND114) U1.R11(GND115) U1.R13(GND116) U1.R15(GND117) U1.R16(GND118) U1.R19(GND119) U1.R21(GND120) U1.R22(GND121) U1.R24(GND122) U1.R25(GND123) U1.T4(GND124) U1.T8(GND125) U1.T10(GND126) U1.T12(GND101) U1.T14(GND127) U1.T16(GND128) U1.T17(GND129) U1.T18(GND130) U1.T19(GND131) U1.T21(GND132) U1.T23(GND133) U1.T24(GND134) U1.T26(GND135) U1.U9(GND136) U1.U11(GND137) U1.U14(GND138) U1.U15(GND139) U1.U16(GND140) U1.U19(GND141) U1.U21(GND142) U1.U24(GND143) U1.V8(GND144) U1.V10(GND145) U1.V12(GND146) U1.V13(GND147) U1.V16(GND148) U1.V19(GND149) U1.V21(GND150) U1.V22(GND151) U1.V24(GND152) U1.V25(GND153) U1.W3(GND154) U1.W9(GND155) U1.W11(GND156) U1.W13(GND157) U1.W15(GND158) U1.W17(GND159) U1.W18(GND160) U1.W19(GND161) U1.W21(GND162) U1.W23(GND163) U1.W24(GND164) U1.W26(GND165) U1.Y8(GND166) U1.Y10(GND167) U1.Y12(GND168) U1.Y14(GND169) U1.Y16(GND170) U1.Y19(GND171) U1.Y21(GND172) U1.Y24(GND173) U5.4(GND) U6.1(A0) U6.2(A1) U6.4(VSS) U6.7(WP) U7.5(GND) U9.46(GND1) U9.47(GND2) U9.69(GND7) U9.75(GND8) U9.77(GND9) U9.80(GND10) U9.107(GND4) U9.109(GND5) U9.123(GND6) U9.129(EPAD) U10.3(AGND) U10.5(PGND) U11.3(AGND) U11.5(PGND) U96.2(GND) U97.2(GND) X3.2 X3.4 ; also on sheet 1 2 10 11 12 22 23 24 25 26 27 28 29 30 31 32 33 34 35 36 37 38 39 40 41 42 43 44 45 46 47 48 49 50 51 52 53 54
V0P9: C125.1 C144.1 C167.1 C188.1 C209.1 L10.2 L14.2 L18.2 L22.2 L26.2 ; also on sheet 30
V0P87_CORE: C156.1 C166.1 C177.1 C187.1 C198.1 C208.1 C219.1P C220.1P C221.1P C222.1P C223.1P C234.1 C235.1 C236.1 C237.1 C238.1 C239.1 C240.1 C241.1 C242.1 C243.1 C244.1 C245.1 C246.1 C247.1 C248.1 C249.1 C250.1 C251.1 C252.1 C253.1 C254.1 C255.1 C256.1 C257.1 C258.1 C259.1 C260.1 C261.1 C262.1 C263.1 C264.1 C265.1 C266.1 C267.1 C268.1 C269.1 C270.1 C271.1 C272.1 C273.1 C274.1 C275.1 C276.1 C851.1 C852.1 C853.1 C854.1 C855.1 C856.1 C857.1 C858.1 C859.1 C860.1 C861.1 C862.1 C863.1 C864.1 C865.1 C866.1 C867.1 C868.1 C869.1 C870.1 C871.1 C872.1 C873.1 C874.1 C875.1 C876.1 C877.1 C878.1 L15.2 L17.2 L19.2 L21.2 L23.2 L25.2 R107.1 U1.J10(VDD2) U1.J15(VDD1) U1.K9(VDD3) U1.K11(VDD4) U1.K13(VDD5) U1.K14(VDD6) U1.K15(VDD7) U1.L8(VDD8) U1.L10(VDD9) U1.L12(VDD10) U1.L14(VDD11) U1.M9(VDD12) U1.M11(VDD13) U1.M13(VDD14) U1.M15(VDD15) U1.N10(VDD16) U1.N15(VDD18) U1.N16(VDD19) U1.P11(VDD20) U1.P12(VDD21) U1.P14(VDD22) U1.R1(VDD23) U1.R2(VDD24) U1.R3(VDD25) U1.R4(VDD26) U1.R5(VDD27) U1.R6(VDD28) U1.R7(VDD29) U1.R8(VDD30) U1.R9(VDD31) U1.R10(VDD32) U1.R12(VDD33) U1.R14(VDD34) U1.T9(VDD35) U1.T11(VDD17) U1.T13(VDD36) U1.T15(VDD37) U1.U10(VDD38) U1.U12(VDD39) U1.U13(VDD40) U1.V9(VDD41) U1.V11(VDD42) U1.V14(VDD43) U1.V15(VDD44) U1.W12(VDD45) U1.W14(VDD46) ; also on sheet 50 51 52 54
V1P2_DDR: C277.1P C278.1P C279.1 C280.1 C281.1 C282.1 C283.1 C284.1 C285.1 C286.1 C287.1 C288.1 C289.1 C290.1 C291.1 C292.1 C293.1 C294.1 C295.1 C296.1 C297.1 C298.1 C299.1 C300.1 C301.1 C302.1 C303.1 C304.1 C305.1 C306.1 C307.1 C308.1 C309.1 C310.1 C311.1 C312.1 C313.1 C314.1 C315.1 C316.1 C317.1 C318.1 C319.1 C320.1 C321.1 C322.1 U1.A14(VDD_DDR7) U1.A17(VDD_DDR8) U1.B8(VDD_DDR9) U1.C7(VDD_DDR10) U1.C9(VDD_DDR11) U1.C12(VDD_DDR5) U1.C13(VDD_DDR12) U1.C14(VDD_DDR13) U1.C18(VDD_DDR14) U1.D10(VDD_DDR15) U1.D15(VDD_DDR2) U1.D17(VDD_DDR16) U1.E6(VDD_DDR17) U1.E8(VDD_DDR18) U1.E13(VDD_DDR3) U1.F4(VDD_DDR19) U1.F11(VDD_DDR1) U1.F13(VDD_DDR4) U1.F18(VDD_DDR20) U1.G3(VDD_DDR21) U1.G6(VDD_DDR22) U1.G7(VDD_DDR23) U1.G9(VDD_DDR24) U1.H9(VDD_DDR25) U1.H11(VDD_DDR26) U1.H13(VDD_DDR27) U1.H15(VDD_DDR28) U1.H17(VDD_DDR6) U1.H20(VDD_DDR29) U1.J7(VDD_DDR30) U1.J8(VDD_DDR31) U1.J12(VDD_DDR32) U1.J14(VDD_DDR33) U1.K6(VDD_DDR34) U1.L3(VDD_DDR35) U1.M4(VDD_DDR36) ; also on sheet 11 12 30
V1P2_ETHSW: C351.1(A[0]) C352.1(A[0]) C353.1(A[0]) C354.1(A[0]) C355.1(A[0]) C356.1(A[0]) C357.1(A[0]) C358.1(A[0]) C359.1(A[0]) FB4.2 R877.2 TP7.1(TP) U9.11(DVDDL1) U9.23(DVDDL8) U9.45(DVDDL7) U9.56(DVDDL6) U9.66(DVDDL9) U9.70(DVDDL10) U9.87(DVDDL4) U9.104(DVDDL3) U9.110(DVDDL2)
V1P2_ETHSW_DC: C360.1 L27.2 R153.2 R877.1 U10.4(OUT)
V1P5: C136.1 C157.1 C178.1 C199.1 L12.2 L16.2 L20.2 L24.2 ; also on sheet 26 27 31 51
V2P5_ETHSW: FB5.1 R878.2 R890.2 TP9.1(TP)
V2P5_ETHSW_DC: C366.1 L28.2 R155.2 R878.1 U11.4(OUT)
V3P3: C135.1 C143.1 C324.1 C327.1 D7.3(A2) L11.2 L13.2 R119.1 R120.2 R121.2 R124.2 R125.2 R126.2 R127.2 R788.1 R793.1 R794.1 R799.1 R802.1 R804.1 R806.1 R808.1 U6.8(VCC) U7.1(VDD) ; also on sheet 10 11 12 22 24 25 26 27 29 30 31 32 33 34 35 43 45 49 51 53 54
V3P3_TIVA_LT: C350.1 C361.1(A[0]) C362.1(A[0]) C363.1(A[0]) C364.1(A[0]) C365.1 R148.1 R150.2 R152.1 R156.2 R158.1 R159.2 R768.1 U9.61(VDDIO1) U9.68(VDDIO3) U9.99(VDDIO2) U10.1(EN) U10.7(VIN) U11.1(EN) U11.7(VIN) ; also on sheet 1 2 28 29 31 37 38 39 40 42 43 44 46 47 52 54
V5P0: R134.1 R137.1 ; also on sheet 25 29 30 31 33 38 49
V12P0: R135.1 R136.1 R948.1 R949.1 ; also on sheet 28 31
V12P0_PSU: J31.19 J31.22 R948.2 R949.2
BOOT_METHOD_GPIO_0: R807.1 R808.2 ; also on sheet 1 12
BOOT_METHOD_GPIO_1: R805.1 R806.2 ; also on sheet 1 12
BOOT_METHOD_GPIO_2: R803.1 R804.2 ; also on sheet 1 12
BOOT_METHOD_GPIO_3: R801.1 R802.2 ; also on sheet 1 12
CHASIS_GND: C371.1 ; also on sheet 2 25 28
CORE_SENSE_MINUS: R108.2 R110.1 ; also on sheet 52
CORE_SENSE_PLUS: R107.2 R109.2 ; also on sheet 52
DIODE_L_N: C328.2 FB3.2 U7.3(DN)
DIODE_L_P: C328.1 FB2.2 U7.2(DP)
ETHSW_GPIO: R772.1 ; also on sheet 53
ETHSW_GPIO1: R772.2 U9.90(GPIO1)
ETHSW_INT_TIVA: R148.2 U9.94(INTRP_N) ; also on sheet 37
ETHSW_LED_G1: J31.15 U9.105(LED1_0)
ETHSW_LED_G2: J31.26 U9.91(LED2_0)
ETHSW_LED_G5: J5.11 U9.102(LED5_0)
ETHSW_LED_Y1: J31.14 U9.106(LED1_1)
ETHSW_LED_Y2: J31.27 U9.92(LED2_1)
ETHSW_LED_Y5: J5.9 U9.103(LED5_1)
ETHSW_RESETN: R147.2 U9.96(RESET_N) ; also on sheet 40
ETHSW_SYNCLK_OUT: R771.1 ; also on sheet 45
ETHSW_TIVA_IBA: U9.67(IBA) ; also on sheet 1
ETHSW_TIVA_P0_TXN: U9.35(TXRX4M_A) ; also on sheet 36
ETHSW_TIVA_P0_TXP: U9.34(TXRX4P_A) ; also on sheet 36
ETHSW_TIVA_PME_N: R768.2 U9.93(PME_N) ; also on sheet 1
FLTR_ OCT_USB0_DVDD_0P85V: C152.1 C153.1 C154.1 C155.1 L15.1 U1.J17(USB0_DVDD)
FLTR_ OCT_USB0_VDD33: C131.1 C132.1 C133.1 C134.1 L11.1 U1.K17(USB_VDD33_1)
FLTR_ OCT_USB0_VP_0P85V: C162.1 C163.1 C164.1 C165.1 L17.1 U1.L18(USB0_VP)
FLTR_ OCT_USB0_VPTX_0P85V: C173.1 C174.1 C175.1 C176.1 L19.1 U1.K18(USB0_VPTX)
FLTR_ OCT_USB1_DVDD_0P85V: C183.1 C184.1 C185.1 C186.1 L21.1 U1.M17(USB1_DVDD)
FLTR_ OCT_USB1_VDD33: C140.1 C141.1 C142.1 C150.1 L13.1 U1.L17(USB_VDD33_2)
FLTR_ OCT_USB1_VP_0P85V: C194.1 C195.1 C196.1 C197.1 L23.1 U1.M19(USB1_VP)
FLTR_ OCT_USB1_VPTX_0P85V: C204.1 C205.1 C206.1 C207.1 L25.1 U1.M18(USB1_VPTX)
FLTR_VDD_DLMC_0P9V: C210.1 C211.1 C212.1 C213.1 C214.1 L26.1 R114.2 U1.AA15(VDD_DLMC2) U1.Y15(VDD_DLMC1)
FLTR_VDDA_QLM0_0P9V: C126.1 C127.1 C128.1 C129.1 C130.1 L10.1 U1.N20(VDDA_DLM0_1) U1.P20(VDDA_DLM0_2)
FLTR_VDDA_QLM1_0P9V: C145.1 C146.1 C147.1 C148.1 C151.1 L14.1 U1.U20(VDDA_DLM1_1) U1.V20(VDDA_DLM1_2)
FLTR_VDDA_QLM2_0P9V: C168.1 C169.1 C170.1 C171.1 C172.1 L18.1 U1.W20(VDDA_DLM2_1) U1.Y20(VDDA_DLM2_2)
FLTR_VDDA_QLM3_0P9V: C189.1 C190.1 C191.1 C192.1 C193.1 L22.1 U1.AC18(VDDA_DLM3_1) U1.AC19(VDDA_DLM3_2)
FLTR_VDDHV_QLM0_1P5V: C137.1 C138.1 C139.1 C149.1 L12.1 U1.R20(VDDHV_DLM0)
FLTR_VDDHV_QLM1_1P5V: C158.1 C159.1 C160.1 C161.1 L16.1 U1.T20(VDDHV_DLM1)
FLTR_VDDHV_QLM2_1P5V: C179.1 C180.1 C181.1 C182.1 L20.1 U1.AA20(VDDHV_DLM2)
FLTR_VDDHV_QLM3_1P5V: C200.1 C201.1 C202.1 C203.1 L24.1 U1.AC20(VDDHV_DLM3)
GPIO10: R798.1 R799.2 ; also on sheet 12
GPIO12: R800.2 ; also on sheet 12
LED3_1: R150.1 R917.2 U9.89(LED3_1)
LED4_1: R151.2 U9.86(LED4_1)
OCT_PLL_MUL0: R797.2 ; also on sheet 1 12
OCT_PLL_MUL1: R796.2 ; also on sheet 1 12
OCT_PLL_MUL2: R795.2 ; also on sheet 1 12
OCT_PLL_MUL3: R794.2 ; also on sheet 1 12
OCT_PLL_MUL4: R793.2 ; also on sheet 1 12
OCT_PLL_MUL5: R792.2 ; also on sheet 1 12
OCT_SGMII_RX0_N: C844.2 ; also on sheet 50
OCT_SGMII_RX0_P: C845.2 ; also on sheet 50
OCT_SGMII_TX0_N: U9.78(S_IN7M) ; also on sheet 50
OCT_SGMII_TX0_P: U9.79(S_IN7P) ; also on sheet 50
OCT_SYS_PLL_PMUL0: R791.2 ; also on sheet 1 12
OCT_SYS_PLL_PMUL1: R790.2 ; also on sheet 1 12
OCT_SYS_PLL_PMUL2: R789.2 ; also on sheet 1 12
OCT_SYS_PLL_PMUL3: R788.2 ; also on sheet 1 12
OCT_SYS_PLL_PMUL4: R787.2 ; also on sheet 1 12
OCT_THERMAL_D_N: FB3.1 ; also on sheet 12
OCT_THERMAL_D_P: FB2.1 ; also on sheet 12
OCT_TWS1_SCL: R122.2 R131.1 U5.6(SCL) ; also on sheet 11 26 27 48 52 53
OCT_TWS1_SDA: R123.2 R130.1 U5.5(SDA) ; also on sheet 11 26 27 48 52 53
OCT_UART0_RTS_L: R116.2 ; also on sheet 53
OCT_UART1_RTS_L: R117.2 ; also on sheet 53
P1_ETHSW_D0N: J31.3 U9.2(TXRX1M_A)
P1_ETHSW_D0P: J31.2 U9.1(TXRX1P_A)
P1_ETHSW_D1N: J31.6 U9.5(TXRX1M_B)
P1_ETHSW_D1P: J31.5 U9.4(TXRX1P_B)
P1_ETHSW_D2N: J31.9 U9.7(TXRX1M_C)
P1_ETHSW_D2P: J31.8 U9.6(TXRX1P_C)
P1_ETHSW_D3N: J31.12 U9.9(TXRX1M_D)
P1_ETHSW_D3P: J31.11 U9.8(TXRX1P_D)
P2_ETHSW_D0N: J31.38 U9.13(TXRX2M_A)
P2_ETHSW_D0P: J31.39 U9.12(TXRX2P_A)
P2_ETHSW_D1N: J31.35 U9.16(TXRX2M_B)
P2_ETHSW_D1P: J31.36 U9.15(TXRX2P_B)
P2_ETHSW_D2N: J31.32 U9.18(TXRX2M_C)
P2_ETHSW_D2P: J31.33 U9.17(TXRX2P_C)
P2_ETHSW_D3N: J31.29 U9.21(TXRX2M_D)
P2_ETHSW_D3P: J31.30 U9.20(TXRX2P_D)
P3_ETHSW_D0N: U9.25(TXRX3M_A) ; also on sheet 23
P3_ETHSW_D0P: U9.24(TXRX3P_A) ; also on sheet 23
P3_ETHSW_D1N: U9.27(TXRX3M_B) ; also on sheet 23
P3_ETHSW_D1P: U9.26(TXRX3P_B) ; also on sheet 23
P3_ETHSW_D2N: U9.29(TXRX3M_C) ; also on sheet 23
P3_ETHSW_D2P: U9.28(TXRX3P_C) ; also on sheet 23
P3_ETHSW_D3N: U9.32(TXRX3M_D) ; also on sheet 23
P3_ETHSW_D3P: U9.31(TXRX3P_D) ; also on sheet 23
P5_D0N_RJ45: J5.2 T1.13(MX4-) U96.3(IO2)
P5_D0P_RJ45: J5.1 T1.14(MX4+) U96.1(IO1)
P5_D1N_RJ45: J5.6 T1.16(MX3-) U96.4(IO3)
P5_D1P_RJ45: J5.3 T1.17(MX3+) U96.6(IO4)
P5_D2N_RJ45: J5.5 T1.19(MX2-) U97.3(IO2)
P5_D2P_RJ45: J5.4 T1.20(MX2+) U97.1(IO1)
P5_D3N_RJ45: J5.8 T1.22(MX1-) U97.4(IO3)
P5_D3P_RJ45: J5.7 T1.23(MX1+) U97.6(IO4)
P5_ETHSW_D0N: T1.12(TD4-) U9.113(TXRX5M_A)
P5_ETHSW_D0P: T1.11(TD4+) U9.112(TXRX5P_A)
P5_ETHSW_D1N: T1.9(TD3-) U9.116(TXRX5M_B)
P5_ETHSW_D1P: T1.8(TD3+) U9.115(TXRX5P_B)
P5_ETHSW_D2N: T1.6(TD2-) U9.118(TXRX5M_C)
P5_ETHSW_D2P: T1.5(TD2+) U9.117(TXRX5P_C)
P5_ETHSW_D3N: T1.3(TD1-) U9.121(TXRX5M_D)
P5_ETHSW_D3P: T1.2(TD1+) U9.120(TXRX5P_D)
POWER_FAN1: J3.1(12V) R134.2 R135.2
POWER_FAN2: J4.2(12V) R136.2 R137.2
PWM_OUT0: Q7.1(G) R124.1 U7.4(PWM)
PWM_OUT1: Q8.1(G) R126.1
RGMII_P6_RXCLK: R143.1 ; also on sheet 50
RGMII_P6_RXCTRL: R141.1 ; also on sheet 50
RGMII_P6_RXD0: R142.1 ; also on sheet 50
RGMII_P6_RXD1: R146.1 ; also on sheet 50
RGMII_P6_RXD2: R145.1 ; also on sheet 50
RGMII_P6_RXD3: R144.1 ; also on sheet 50
RGMII_P6_TXCLK: U9.48(TX_CLK6/REFCLKI6) ; also on sheet 50
RGMII_P6_TXCTRL: U9.49(TX_EN6/TX_CTL6) ; also on sheet 50
RGMII_P6_TXD0: U9.55(TXD6_0) ; also on sheet 50
RGMII_P6_TXD1: U9.54(TXD6_1) ; also on sheet 50
RGMII_P6_TXD2: U9.53(TXD6_2) ; also on sheet 50
RGMII_P6_TXD3: U9.52(TXD6_3) ; also on sheet 50
RTC_IRQ: R120.1 U5.7(IRQ1_L) ; also on sheet 10
RTC_XTAL_IN: C325.1 U5.1(X1) X2.1
RTC_XTAL_OUT: C326.1 U5.2(X2) X2.2
SYNCE_CLK: R773.1 ; also on sheet 45
SYNCLK_OUT: R771.2 U9.95(SYNCLKO)
TACH0: C329.2 R125.1 U7.6(ALERT#/TACH)
TACH1: J4.1(ROT) R127.1 R138.2
TIVA_ETHSW_P0_RXN: U9.38(TXRX4M_B) ; also on sheet 36
TIVA_ETHSW_P0_RXP: U9.37(TXRX4P_B) ; also on sheet 36
TIVA_GPIO_PL5: J31.24 ; also on sheet 37
TIVA_GPIO_PM6: J31.23 ; also on sheet 37
TIVA_I2C0_SCLK: U9.101(SCL/MDC) ; also on sheet 37 52
TIVA_I2C0_SDA: U9.98(SDI/SDA/MDIO) ; also on sheet 37 52
TIVA_UART6_RX: J31.17 ; also on sheet 37
TIVA_UART6_TX: J31.18 ; also on sheet 37
TRCT1: C367.1 T1.1(TCT1)
TRCT2: C368.1 T1.4(TCT2)
TRCT3: C369.1 T1.7(TCT3)
TRCT4: C370.1 T1.10(TCT4)
TWS1_EEPROM_SCL: R122.1 U6.6(SCL)
TWS1_EEPROM_SDA: R123.1 U6.5(SDA)
TWS1_FAN_SCL: R131.2 U7.8(SMBCLK)
TWS1_FAN_SDA: R130.2 U7.7(SMBDAT)
VA1P2_ETHSW: C340.1(A[0]) C341.1(A[0]) C342.1(A[0]) C343.1(A[0]) C344.1(A[0]) C345.1(A[0]) C346.1(A[0]) C347.1(A[0]) C348.1(A[0]) C349.1(A[0]) FB4.1 U9.3(AVDDL1) U9.14(AVDDL2) U9.19(AVDDL3) U9.30(AVDDL4) U9.36(AVDDL5) U9.41(AVDDL6) U9.71(VDDLS1) U9.84(VDDLS2) U9.114(AVDDL7) U9.119(AVDDL8) U9.124(AVDDL9)
VA2P5_ETHSW: C332.1(A[0]) C333.1(A[0]) C334.1(A[0]) C335.1(A[0]) C336.1(A[0]) C337.1(A[0]) C338.1(A[0]) C339.1(A[0]) C846.1(A[0]) C847.1(A[0]) FB5.2 U9.10(AVDDH7) U9.22(AVDDH6) U9.33(AVDDH5) U9.44(AVDDH4) U9.72(VDDHS1) U9.83(VDDHS2) U9.111(AVDDH3) U9.122(AVDDH2) U9.128(AVDDH1)
N298352: R121.1 TP6.1 U5.3(IRQ2_L)
N298422: C323.1 D7.1(C) U5.8(VDD)
N299772: BT1.1(+) R118.2
N18275850: D7.2(A1) R118.1
N25953160: R109.1 U1.N13(VDD_SEN+)
N25953174: R108.1 U1.N14(VDD_SEN-)
N30789098: C331.1(A[0]) R774.1 X3.1
N30789100: C330.1(A[0]) R775.1 X3.3
N30789228: R774.2 U9.125(XO)
N30789242: R773.2 R775.2 U9.126(XI)
N30820120: R149.2 U9.127(ISET)
N30859692: R143.2 U9.57(RX_CLK6/REFCLKO6)
N30859805: R142.2 U9.65(RXD6_0)
N30859816: R146.2 U9.64(RXD6_1)
N30859819: R145.2 U9.63(RXD6_2)
N30859822: R144.2 U9.62(RXD6_3)
N30859857: R141.2 U9.58(RX_DV6/CRS_DV6/RX_CTL6)
N30860787: R155.1 R157.2 U11.2(FB)
N30860853: L28.1 U11.6(SW)
N30860857: R156.1 U11.8(PG)
N30861542: R153.1 R154.2 U10.2(FB)
N30861608: L27.1 U10.6(SW)
N30861612: R152.2 U10.8(PG)
N31612864: R119.2 U6.3(A2)
N31614278: C329.1 Q7.3(S) R139.2
N31614280: J3.2(GND) Q7.2(D1) Q7.4(D2)
N31614677: J4.3(GND) Q8.2(D1) Q8.4(D2)
N31614705: Q8.3(S) R138.1 R140.2
N32443893: R769.2 U9.76(S_REXT)
N32444061: C845.1 U9.81(S_OUT7P)
N32444064: C844.1 U9.82(S_OUT7M)
N33770718: C371.2 R160.1 R161.1 R162.1 R163.1
N33770728: R163.2 T1.24(MCT1)
N33770730: R162.2 T1.21(MCT2)
N33770732: R160.2 T1.15(MCT4)
N33770742: R161.2 T1.18(MCT3)
N33771166: J5.10 R158.2
N33771170: J5.12 R159.1
N34195454: D38.A R890.1

Not connected (* = marked no-connect by the designer): U9 39(TXRX4P_C)* 40(TXRX4M_C)* 42(TXRX4P_D)* 43(TXRX4M_D)* 50(TX_ER6)* 51(COL6)* 59(RX_ER6)* 60(CRS6)* 73(NC3)* 74(NC4)* 85(LED4_0) 88(LED3_0) 97(SDO) 100(SCS_N) 108(NC2)*; U96 5(VCC)*; U97 5(VCC)*

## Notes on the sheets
sheet 13
- Place close to U1
sheet 14
- Place close to the
  filter
- Place close to the
  filter
- Place close to
  the device
- Place close to
  the device
- Place close to the
  filter
- Place close to the
  filter
- Place close to
  the device
- Place close to the
  filter
- Place close to
  the device
- Place close to the
  filter
- Place close to the
  filter
- Place close to
  the device
- Place close to
  the device
- Place close to the
  filter
- Place close to
  the device
- Place close to the
  filter
- Place close to
  the device
- Place close to the
  filter
- Place close to the
  filter
- Place close to
  the device
- Place close to
  the device
- Place close to the
  filter
- Place close to
  the device
- Place close to the
  filter
- Place close to
  the device
- Place close to the
  filter
- Place close to the
  filter
- Place close to
  the device
- Place close to
  the device
- Place close to the
  filter
- Place close to
  the device
- Place close to the
  filter
- Place close to
  the device
- Place close to
  the device
sheet 16
- Delete C215~C218
- 5 x 330uF
- 8 x 100uF
- 7 x 22uF
- 15 x 1uF
- 13 x 0.1uF
- 15 x 1uF
- 13 x 0.1uF
- ADDED
- Layout Note: Use 10 mil for power vias
- 2 x 330uF
- 4 x 100uF
- 4 x 22uF
- 18 x 1uF
- 18 x 0.1uF
- This page is for reference only and NOT for AS IS use.
  Users of this page of the schematics need to confirm
  the validity of similar circuitry in the user's application.
sheet 17
- CN81xx Strapping
- Coprocessor-clock (SCLK) PLL multiplier
- Core-clock (RCLK) PLL multiplier
- RST Boot-strap Method Enumeration
- [0]
- GPIO_13
- [0]
- [0]
- GPIO_19
- GPIO_0
- [1]
- [1]
- GPIO_14
- [1]
- GPIO_20
- GPIO_1
- [2]
- [2]
- GPIO_15
- [2]
- GPIO_21
- GPIO_2
- [3]
- [3]
- GPIO_22
- GPIO_16
- [3]
- GPIO_3
- [4]
- [4]
- GPIO_17
- Description :
- GPIO_23
- 0 0 1 0
- = EMMC_SS
- = EMMC_LS
- (Default boot from SD
- [5]
- 0 0 1 1
- Description :
- GPIO_18
- 0 1 0 1
- = SPI24
- 0 0 0 0 1
- = 350 MHz.
- Description :
- 0 1 1 0
- = SPI32
- 0 0 0 1 0
- = 400 MHz.
- 0 0 0 0
- 0 1 1 0
- = 600 MHz.
- 1 0 0 0
- = REMOTE
- 0 0 0 1 1
- = 450 MHz.
- 0 0 0 0
- 1 0 1 0
- = 800 MHz.
- 1 0 0 1
- = CCPI0
- 0 0 1 0 0
- = 500 MHz
- 0 0 0 0
- 1 1 1 0
- = 1000 MHz.
- 1 0 1 0
- = CCPI1
- 0 0 1 0 1
- = 550 MHz.
- 0 0 0 1
- 0 0 1 0
- = 1200 MHz.
- 1 0 1 1
- = CCPI2
- 0 0 1 1 0
- = 600 MHz.
- 0 0 0 1
- 0 1 1 0
- = 1400 MHz.
- 1 1 0 0
- = PCIE0
- 0 0 1 1 1
- = 650 MHz.
- 0 0 0 1
- 1 0 0 0
- = 1500 MHz.
- (DEFAULT)
- 1 1 0 1
- = PCIE2
- 0 1 0 0 0
- = 700 MHz. (DEFAULT)
- 0 0 0 1
- 1 0 1 0
- = 1600 MHz.
- 0 0 0 1
- 1 1 1 0
- = 1800 MHz.
- 0 0 1 0
- 0 0 1 0
- = 2000 MHz.
- OCT_UART0_RTS_L = 1
  OCT_UART1_RTS_L = 1
  PLL SOURCE = PLL_REF_CLK
- Trusted-mode
- GPIO_12
- GPIO_10
- Description :
- During flash boot, reserved.
  Post-boot, free for board use.
- 0 = Non-trusted boot.
- 1 = Trusted boot.
sheet 18
- RTC
- TLV EEPROM
- I2C ADDRESS = 0x54
- Temperature Sensor & Fan
  Controller
- I2C ADDRESS = 0x4C
- Chassis
  Fan Header
- Layout Notes:
  Resistors should
  be of 3 pin so
  only one can
  populate
- BGA
  Fan Header
sheet 19
- PORT 6  RGMII MODE
- RGMII TX length match:
  RGMII_P6_TXD[0:3],TXCTRL,±20mil, TXCLK should 2.5inch longer than TXCTRL
- PORT 5-1 1000BASE-T DIFF
- RGMII RXlength match:
  RGMII_P6_RXD[0:3],RXCTRL,RXCLK,should be ±20mil,
- INPUT
- input
- PORT1 TO POWER BOARD
- output
- output
- input
- PORT2 TO POWER BOARD
- output
- PORT3  TO  GBC CONNECTOR
- 0: disable in-band management default
- PORT4 TO TIVA
- TIVA only support 100M-BASE
- PORT5 TO RJ46
- reset controlled
  by tiva
- to IDT PLL
- to 81xx GPIO
- PORT1 LED
- led1_1=1:Flow control: enable
- led2_1=1:normal link-up
- PORT2 LED
- auto-negotiation :enable
- LED1_1/LED2_1/LED3_1
  LED4_0/LED4_1/LED5_1  is IPU
- from IDT pll
- LED4_1   LED3_1
- Manage IF
- 0
- 0
- MDIO
- 0
- 1
- I2C
- default
- IIC ADDR: 0X5F
- 1
- X
- SPI
- 2
- 1
sheet 20
- decoupling caps should place close to the power pin
- decoupling caps should place close to the power pin
- decoupling caps should place close to the power pin
- (2A)
- R1218 JUMPER
- (2A)
- decoupling caps should place close to the power pin
- R1218 JUMPER
sheet 21
- FOR DEBUG ONLY
